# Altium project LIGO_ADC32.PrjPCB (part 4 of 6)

## Sheet AD32_PHASE.SchDoc: VCO & Phase Detector
size B; DocumentNumber: 1; Revision: C; SheetNumber: 2; SheetTotal: 17; SPICEModelCacheGRPSJKPR: <root> / <DocumentId>GRPSJKPR</DocumentId> / <CacheFrame Number="0"> / <Model Name="op284f" Kind="CKT"> / <Text>* OP284F SPICE Macro-model              11/95 / Rev. B / *                                       ARG / ADSC / * / * Revision History: / * / *     Rev. B / * Changed the short-circuit output current limit from +/- 7.5mA / * to +/- 6.5mA to reflect final data sheet limits. / * / * Changed Vos spec to conform to final data sheet value of / * 125uV, up from 50uV. / * / * / * This version of the OP284 model simulates the worst-case / * parameters of the 'F' grade.  The worst-case parameters / * used correspond to those in the data sheet. / * / * Copyright 1993 by Analog Devices / * / * Refer to "README.DOC" file for License Statement. Use of this model / * indicates your acceptance of the terms and provisions in the License / * Statement. / * / * Node assignments / *                non-inverting input / *                ¦   inverting input / *                ¦   ¦   positive supply / *                ¦   ¦   ¦   negative supply / *                ¦   ¦   ¦   ¦   output / *                ¦   ¦   ¦   ¦   ¦ / .SUBCKT OP284F   1   2   99  50  45 / * / * INPUT STAGE / * / Q1   5    2    3    QIN 1 / Q2   6    11   3    QIN 1 / Q3   7    2    4    QIP 1 / Q4   8    11   4    QIP 1 / DC1  2    11   DC / DC2  11   2    DC / Q5   4    9    99   QIP 1 / Q6   9    9    99   QIP 1 / Q7   3    10   50   QIN 1 / Q8   10   10   50   QIN 1 / R1   99   5    4E3 / R2   99   6    4E3 / R3   7    50   4E3 / R4   8    50   4E3 / IREF 9    10   50.5E-6 / EOS  1    11   POLY(2) (22,98) (14,98) -125E-6 501.2E-3 1 / IOS  2    1    25E-9 / CIN  1    2    2E-12 / GN1  98   1    17 98 1E-3 / GN2  98   2    23 98 1E-3 / * / * VOLTAGE NOISE SOURCE WITH FLICKER NOISE / * / VN1  13   98   DC 2 / VN2  98   15   DC 2 / DN1  13   14   DEN / DN2  14   15   DEN / * / * CURRENT NOISE SOURCE WITH FLICKER NOISE / * / VN3  16   98   DC 2 / VN4  98   18   DC 2 / DN3  16   17   DIN / DN4  17   18   DIN / * / * 2ND CURRENT NOISE SOURCE WITH FLICKER NOISE / * / VN5  19   98   DC 2 / VN6  98   24   DC 2 / DN5  19   23   DIN / DN6  23   24   DIN / * / * GAIN STAGE / * / EREF 98   0    POLY(2) (99,0) (50,0) 0 0.5 0.5 / G1   98   20   POLY(2) (6,5) (8,7) 0 0.5E-3 0.5E-3 / R9   20   98   1E3 / * / * COMMON MODE STAGE WITH ZERO AT 5KHZ / * / ECM  98   21   POLY(2) (1,98) (2,98) 0 0.5 0.5 / R10  21   22   1 / R11  22   98   100E-6 / C4   21   22   31.756E-6 / * / * NEGATIVE ZERO AT 20MHZ / * / E1   27   98   20 98 1 / R17  27   28   1 / R18  28   98   1E-6 / C8   25   26   7.958E-9 / ENZ  25   98   27 28 1 / VNZ  26   98   DC 0 / FNZ  27   28   VNZ -1 / * / * POLE AT 40MHZ / * / G4   98   29   28 98 1E6 / R19  29   98   1 / C9   29   98   3.979E-9 / * / * POLE AT 40MHZ / * / G5   98   30   29 98 1 / R20  30   98   1 / C10  30   98   3.979E-9 / * / * OUTUT STAGE / * / ISY  99   50   0.526E-3 / GIN  50   31   POLY(1) (30,98) 0.862574E-6 511.855E-6 / RIN  31   50   2.75E6 / VB   99   32   0.7 / Q11  32   31   33   QON 1 / R21  33   34   4.5E3 / I1   34   50   50E-6 / R22  99   35   6E3 / Q12  36   36   35   QOP 1 / I2   36   50   50E-6 / R23  99   37   2.6E3 / R24  34   38   5E3 / Q13  39   36   37   QOP 1 / Q14  39   38   40   QON 1.5 / R25  40   50   40 / Q15  39   39   41   QON 1 / R26  41   42   1E3 / R27  99   43   220 / Q16  44   44   43   QOP 1.5 / Q17  44   39   42   QON 1 / R28  42   50   2E3 / VSCP 99   97   DC 0 / FSCP 46   99   VSCP 1 / RSCP 46   99   125 / Q20  44   46   99   QOP 1 / Q18  45   44   97   QOP 4.5 / Q19  45   34   51   QON 4.5 / VSCN 51   50   DC 0 / FSCN 50   47   VSCN 1 / RSCN 47   50   122 / Q21  34   47   50   QON 1 / CC2  31   45   20E-12 / CF1  31   34   15E-12 / CF2  31   42   15E-12 / CO1  34   45   15E-12 / CO2  42   45   5E-12 / D3   45   99   DX / D4   50   45   DX / .MODEL DC D(IS=130E-21) / .MODEL DX D() / .MODEL DEN D(RS=100 KF=12E-15 AF=1) / .MODEL DIN D(RS=5.358 KF=56E-15 AF=1) / .MODEL QIN NPN(BF=250 VA=200 IS=0.5E-16) / .MODEL QIP PNP(BF=60 VA=100 IS=0.5E-16) / .MODEL QON NPN(BF=200 VA=200 IS=0.5E-16 RC=140) / .MODEL QOP PNP(BF=200 VA=200 IS=0.5E-16 RC=210) / .ENDS</Text> / </Model> / </CacheFrame> / </root>
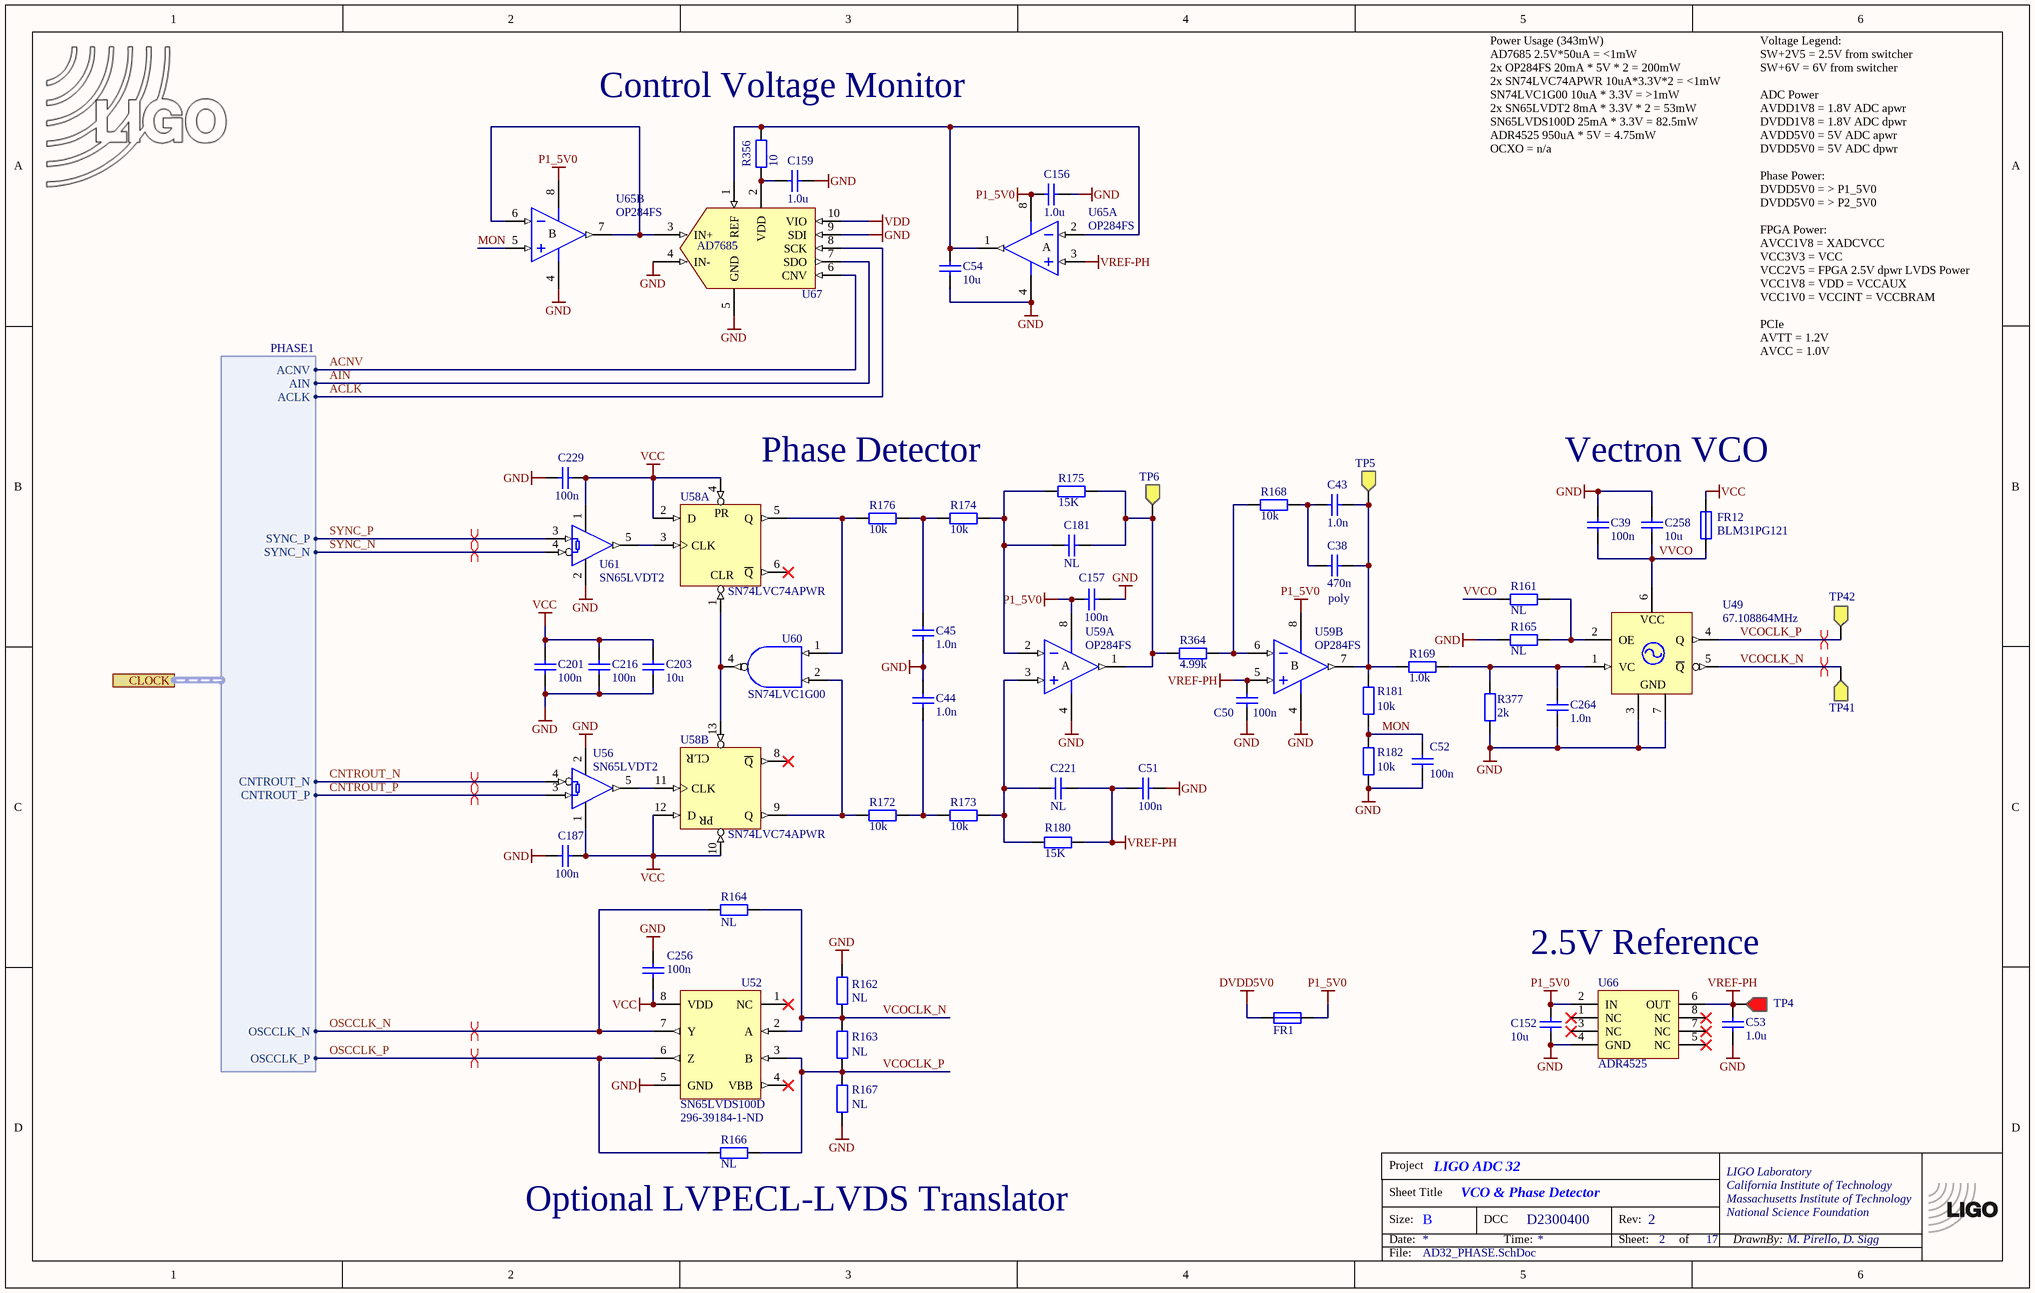
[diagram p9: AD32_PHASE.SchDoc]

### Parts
(Parts that share a designator on the sheet are numbered #1, #2 ... from top to bottom, then left to right.)
*?#6  TitleBlock  (value not drawn)  (graphical)
C38  470n  [ECQPZ120060-5.0]
C39  100n  [CC1005-0402]
C43  1.0n  [CC1005-0402]
C44  1.0n  [CC1005-0402]
C45  1.0n  [CC1005-0402]
C50  100n  [CC1005-0402]
C51  100n  [CC1005-0402]
C52  100n  [CC1005-0402]
C53  1.0u  [CC1608-0603]
C54  10u  [CC2013-0805]
C152  10u  [CC2013-0805]
C156  1.0u  [CC1608-0603]
C157  100n  [CC1005-0402]
C159  1.0u  [CC1608-0603]
C181  NL  [CC2013-0805]
C187  100n  [CC1005-0402]
C201  100n  [CC1005-0402]
C203  10u  [CC2013-0805]
C216  100n  [CC1005-0402]
C221  NL  [CC2013-0805]
C229  100n  [CC1005-0402]
C256  100n  [CC1005-0402]
C258  10u  [CC2013-0805]
C264  1.0n  [CC1005-0402]
FR1  BLM31PG121  [CC3216-1206]  (value not drawn)
FR12  BLM31PG121  [CC3216-1206]
LOGO2#1  LIGO logo  [LIGO_LOGO]  (value not drawn)  (graphical)
R161  NL  [CR1005-0402]
R162  NL  [CR1005-0402]
R163  NL  [CR1005-0402]
R164  NL  [CR1005-0402]
R165  NL  [CR1005-0402]
R166  NL  [CR1005-0402]
R167  NL  [CR1005-0402]
R168  10k  [CR1005-0402]
R169  1.0k  [CR1005-0402]
R172  10k  [CR1005-0402]
R173  10k  [CR1005-0402]
R174  10k  [CR1005-0402]
R175  15K  [CR1005-0402]
R176  10k  [CR1005-0402]
R180  15K  [CR1005-0402]
R181  10k  [CR1005-0402]
R182  10k  [CR1005-0402]
R356  10  [CR1005-0402]
R364  4.99k  [CR1005-0402]
R377  2k  [CR1005-0402]
TP4  Testpoint  [TP1-RED]  (value not drawn)
TP5  Testpoint  [TP1-YLW]  (value not drawn)
TP6  Testpoint  [TP1-YLW]  (value not drawn)
TP41  Testpoint  [TP2]  (value not drawn)
TP42  Testpoint  [TP2]  (value not drawn)
U49  67.108864MHz  [BomarSiTime]
U52  SN65LVDS100D  Supplier Part Number 1: 296-39184-1-ND  [MSOP8]
U56  SN65LVDT2  [SO-G5/E2.4]
U58  SN74LVC74APWR  [TSSOP14]  (parts A,B of 2)
U59  OP284FS  [SO-8_N]  (parts A,B of 2)
U60  SN74LVC1G00  [SO-G5/E2.4]
U61  SN65LVDT2  [SO-G5/E2.4]
U65  OP284FS  [SO-8_N]  (parts A,B of 2)
U66  ADR4525  [SO-G8]
U67  AD7685  [TSSO3x5-G10]

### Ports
CLOCK (harness PHASE1)

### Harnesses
PHASE1: OSCCLK_N, OSCCLK_P, CNTROUT_N, CNTROUT_P, SYNC_N, SYNC_P, ACLK, ACNV, AIN

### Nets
DVDD5V0: FR1.2
GND: C39.1 C44.1 C45.2 C50.1 C51.1 C52.1 C53.1 C54.2 C152.2 C156.1 C157.1 C159.1 C187.1 C201.1 C203.2 C216.1 C229.1 C256.1 C258.1 C264.2 R162.1 R165.1 R167.2 R182.2 R377.2 U49.3(GND1) U49.7(EP) U52.5(GND) U56.2(GND) U58.7(GND) U59.4(V-) U60.3(GND) U61.2(GND) U65.4(V-) U66.4(GND) U67.4(IN-) U67.5(GND) U67.9(SDI)
P1_5V0: C152.1 C156.2 C157.2 FR1.1 U59.8(V+) U65.8(V+) U66.2(IN)
VCC: C187.2 C201.2 C203.1 C216.2 C229.2 C256.2 FR12.2 U52.8(VDD) U56.1(VCC) U58.2(D) U58.4(PR) U58.10(PR) U58.12(D) U58.14(VCC) U60.5(VCC) U61.1(VCC)
VDD: U67.10(VIO)  [project net VCC1V8]
VREF-PH: C50.2 C51.2 C53.2 C221.1 R180.2 TP4.1 U59.5(IN+) U65.3(IN+) U66.6(OUT)
ACLK: U67.8(SCK) ; port CLOCK.ACLK  [project net CLOCK.ACLK]
ACNV: U67.6(CNV) ; port CLOCK.ACNV  [project net CLOCK.ACNV]
AIN: U67.7(SDO) ; port CLOCK.AIN  [project net CLOCK.AIN]
CNTROUT_N: U56.4(B) ; port CLOCK.CNTROUT_N  [project net CLOCK.CNTROUT_N]
CNTROUT_P: U56.3(A) ; port CLOCK.CNTROUT_P  [project net CLOCK.CNTROUT_P]
MON: C52.2 R181.2 R182.1 U65.5(IN+)
OSCCLK_N: R164.1 U52.7(Y) ; port CLOCK.OSCCLK_N  [project net CLOCK.OSCCLK_N]
OSCCLK_P: R166.2 U52.6(Z) ; port CLOCK.OSCCLK_P  [project net CLOCK.OSCCLK_P]
SYNC_N: U61.4(B) ; port CLOCK.SYNC_N  [project net CLOCK.SYNC_N]
SYNC_P: U61.3(A) ; port CLOCK.SYNC_P  [project net CLOCK.SYNC_P]
VCOCLK_N: R162.2 R163.1 R164.2 TP41.1 U49.5(~{Q}) U52.2(A)
VCOCLK_P: R163.2 R166.1 R167.1 TP42.1 U49.4(Q) U52.3(B)
VVCO: C39.2 C258.2 FR12.1 R161.1 U49.6(VDD)
NetC38_1: C38.1 C43.2 R168.2
NetC38_2: C38.2 C43.1 R169.2 R181.1 TP5.1 U59.7(OUT)
NetC44_2: C44.2 R172.2 R173.1
NetC45_1: C45.1 R174.1 R176.2
NetC54_1: C54.1 R356.2 U65.1(OUT) U65.2(IN-) U67.1(REF)
NetC159_2: C159.2 R356.1 U67.2(VDD)
NetC181_1: C181.1 R175.2 R364.1 TP6.1 U59.1(OUT)
NetC181_2: C181.2 R174.2 R175.1 U59.2(IN-)
NetC221_2: C221.2 R173.2 R180.1 U59.3(IN+)
NetC264_1: C264.1 R169.1 R377.1 U49.1(VC)
NetR161_2: R161.2 R165.2 U49.2(OE)
NetR168_1: R168.1 R364.2 U59.6(IN-)
NetR172_1: R172.1 U58.9(Q) U60.2
NetR176_1: R176.1 U58.5(Q) U60.1
NetU56_5: U56.5(R) U58.11(CLK)
NetU58_1: U58.1(CLR) U58.13(CLR) U60.4
NetU58_3: U58.3(CLK) U61.5(R)
NetU65_6: U65.6(IN-) U65.7(OUT) U67.3(IN+)

Not connected (* = marked no-connect by the designer): U52 1(NC)* 4(VBB)*; U58 6(~{Q})* 8(~{Q})*; U66 1(NC)* 3(NC)* 5(NC)* 7(NC)* 8(NC)*

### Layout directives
differential pair: CLOCK.CNTROUT_N, CLOCK.CNTROUT_P, CLOCK.OSCCLK_N, CLOCK.OSCCLK_P, CLOCK.SYNC_N, CLOCK.SYNC_P, VCOCLK_N, VCOCLK_P

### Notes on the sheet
- (near R356) Control Voltage Monitor
- Power Usage (343mW)
  AD7685 2.5V*50uA = <1mW
  2x OP284FS 20mA * 5V * 2 = 200mW
  2x SN74LVC74APWR 10uA*3.3V*2 = <1mW
  SN74LVC1G00 10uA * 3.3V = >1mW
  2x SN65LVDT2 8mA * 3.3V * 2 = 53mW
  SN65LVDS100D 25mA * 3.3V = 82.5mW
  ADR4525 950uA * 5V = 4.75mW
  OCXO = n/a
- Voltage Legend:
  SW+2V5 = 2.5V from switcher
  SW+6V = 6V from switcher
  ADC Power
  AVDD1V8 = 1.8V ADC apwr
  DVDD1V8 = 1.8V ADC dpwr
  AVDD5V0 = 5V ADC apwr
  DVDD5V0 = 5V ADC dpwr
  Phase Power:
  DVDD5V0 = > P1_5V0
  DVDD5V0 = > P2_5V0
  FPGA Power:
  AVCC1V8 = XADCVCC
  VCC3V3 = VCC
  VCC2V5 = FPGA 2.5V dpwr LVDS Power
  VCC1V8 = VDD = VCCAUX
  VCC1V0 = VCCINT = VCCBRAM
  PCIe
  AVTT = 1.2V
  AVCC = 1.0V
- Phase Detector
- Vectron VCO
- poly
- 2.5V Reference
- (near R166) Optional LVPECL-LVDS Translator

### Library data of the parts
C38 = CapPolypropylene ECQPZ: Polypropylene Film Capacitor, radial lead; Part Number: 399-13063-ND
C39 C50-C52 C157 C187 C201 C216 C229 C256 = ChipCap: C0402 100n; Part Number: CL05B104KA5NNNC
C43-C45 C264 = ChipCap: C0402 1.0n; Part Number: 0402N102J250CT
C53 C156 C159 = ChipCap: C0603 1.0u; Part Number: CL10B105KA8NNNC
C54 C152 C203 C258 = ChipCap: C0805 10u; Part Number: CL21A106KAYNNNG
C181 C221 = ChipCap: C0805 NL
FR1 FR12 = BLM31PG121SN1: ferrite bead, 120Ohm at 100MHz, 1206; Part Number: BLM31PG121SN1L
LOGO2#1 = LIGO_logo
R161 R165 = ChipRes1: R0603 NL
R162-R164 R166 R167 = ChipRes1: R0402 NL
R168 R172-R174 R176 R181 R182 = ChipRes1: R0402 10k; Part Number: ERA-2AEB103X
R169 = ChipRes1: R0402 1.0k; Part Number: RT0402BRD071KL
R175 R180 = ChipRes1: R0402 15k; Part Number: ERA-2AEB153X
R356 = ChipRes1: R0402 10; Part Number: RP73PF1E10RBTD
R364 = ChipRes1: R0402 4.99k; Part Number: RR0510P-4991-D
R377 = ChipRes1: R0402 2k; Part Number: ERA-2AEB202X
TP4 = TP_POSITIVE: Testpoint, red; Part Number: Keystone / 5000
TP5 TP6 = TP_SIGNAL: Testpoint, yellow; Part Number: Keystone / 5004
TP41 TP42 = TP_SIGNAL: Part Number: Keystone / 5017
U49 = VCXO_BomarSiTime: Voltage controlled crystal oscillator, differential output, Bomar 14.3 x 8.7mm, or SiTime 7.0 x 5.0mm; Part Number: B1815-BA0S36LK-67.108864; Alternate Part 1: SiT3372AI-1E2-xxxx000.fp0000f; Alternate Part 2: SiT3372AI-2E2-33NC47.934903; Alternate Part 3: C5310-D105-SV033-RFL-B1-67.108864MHz
U52 = SN65LVDS100: DIFF TRANSLATOR
U56 U61 = SN65LVDT2DBV: Single LVDS Receiver with 100 Ohm termination; Part Number: 296-6896-1-ND
U58 = 74F74PC: Dual D-Type Positive Edge-Triggered Flip-Flop
U59 U65 = OP284FS: Precision Rail-to-Rail Input and Output Operational Amplifier; Part Number: OP284FSZ-REEL7
U60 = SN74LVC1G00: Part Number: 74LVC1G00W5-7
U66 = ADR292ER: Low-Noise Micropower Precision Voltage Reference; Part Number: ADR425ARZ-ND
U67 = AD7685: 16 bit ADC, 250kSPS, pseudo differential, serial; Part Number: AD7685BRMZRL7

## Sheet AD32_PCIE_HL.SchDoc: PCIe Interface
size B; Engineer: Daniel Sigg; DocumentNumber: 1; Revision: C; SheetNumber: 16; SheetTotal: 17; PageSetup: Record=PageOptions¦CenterHorizontal=True¦CenterVertical=True¦PrintScale=0.72¦XCorrection=1.00¦YCorrection=1.00¦PrintKind=0¦BorderSize=5000000¦LeftOffset=0¦BottomOffset=0¦Orientation=2¦PaperLength=1000¦PaperWidth=1000¦Scale=100¦PaperSource=7¦PrintQuality=-4¦MediaType=1¦DitherType=10¦PaperKind=Tabloid¦PrintScaleMode=1
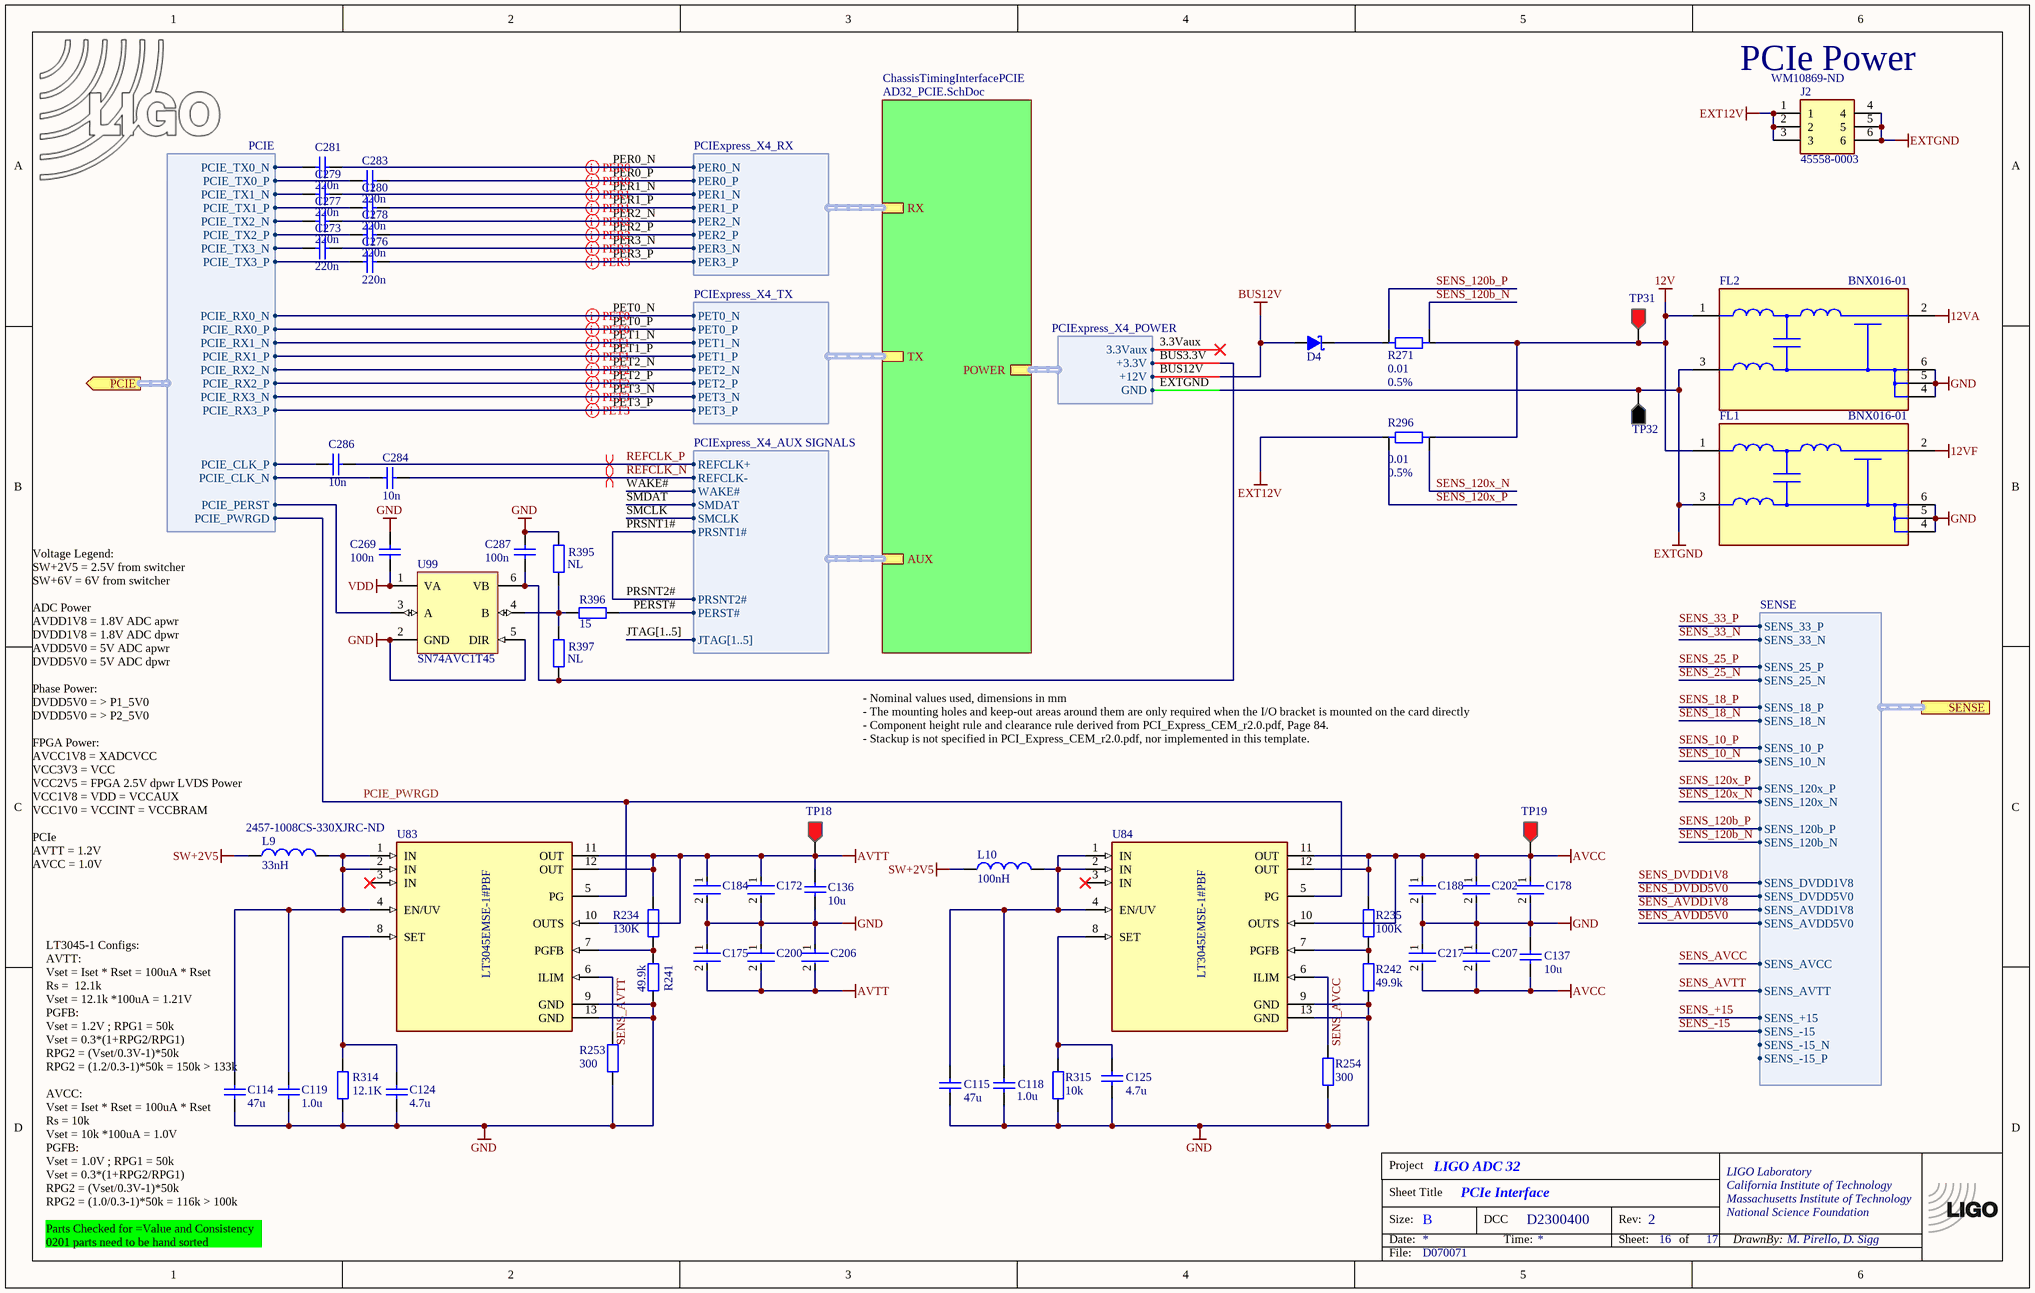
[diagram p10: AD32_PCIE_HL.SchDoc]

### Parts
(Parts that share a designator on the sheet are numbered #1, #2 ... from top to bottom, then left to right.)
*?#7  TitleBlock  (value not drawn)  (graphical)
C114  47u  [CC3216-1206]
C115  47u  [CC3216-1206]
C118  1.0u  [CC1608-0603]
C119  1.0u  [CC1608-0603]
C124  4.7u  [CC1608-0603]
C125  4.7u  [CC1608-0603]
C136  10u  [CC2013-0805]
C137  10u  [CC2013-0805]
C172  470n  [FP-CL03-IPC_B]  (value not drawn)
C175  470n  [FP-CL03-IPC_B]  (value not drawn)
C178  470n  [FP-CL03-IPC_B]  (value not drawn)
C184  470n  [FP-CL03-IPC_B]  (value not drawn)
C188  470n  [FP-CL03-IPC_B]  (value not drawn)
C200  470n  [FP-CL03-IPC_B]  (value not drawn)
C202  470n  [FP-CL03-IPC_B]  (value not drawn)
C206  470n  [FP-CL03-IPC_B]  (value not drawn)
C207  470n  [FP-CL03-IPC_B]  (value not drawn)
C217  470n  [FP-CL03-IPC_B]  (value not drawn)
C269  100n  [CC1005-0402]
C273  220n  [CC1005-0402]
C276  220n  [CC1005-0402]
C277  220n  [CC1005-0402]
C278  220n  [CC1005-0402]
C279  220n  [CC1005-0402]
C280  220n  [CC1005-0402]
C281  220n  [CC1005-0402]
C283  220n  [CC1005-0402]
C284  10n  [CC1005-0402]
C286  10n  [CC1005-0402]
C287  100n  [CC1005-0402]
D4  Schottky SMB  [DO-SMB]  (value not drawn)
FL1  BNX016-01  [FP-BNX_L12MM2_W11MM2_T8MM-MFG]
FL2  BNX016-01  [FP-BNX_L12MM2_W11MM2_T8MM-MFG]
J2  45558-0003  Supplier Part Number 1: WM10869-ND  [455580003]
L9  Supplier Part Number 1: 2457-1008CS-330XJRC-ND  [CL2520-1008]  (hidden comment: 33nH)
L10  100nH  [CL2520-1008]
LOGO?#2  LIGO logo  [LIGO_LOGO]  (value not drawn)  (graphical)
R234  130K  [CR1005-0402]
R235  100K  [CR1005-0402]
R241  49.9k  [CR1005-0402]
R242  49.9k  [CR1005-0402]
R253  300  [CR1005-0402]
R254  300  [CR1005-0402]
R271  Tolerance: 0.5%  [CR0816-0306-4P]  (hidden comment: 0.01)
R296  Tolerance: 0.5%  [CR0816-0306-4P]  (hidden comment: 0.01)
R314  12.1K  [CR1005-0402]
R315  10k  [CR1005-0402]
R395  NL  [CR1005-0402]
R396  15  [CR1005-0402]
R397  NL  [CR1005-0402]
TP18  Testpoint  [TP1-RED]  (value not drawn)
TP19  Testpoint  [TP1-RED]  (value not drawn)
TP31  Testpoint  [TP1-RED]  (value not drawn)
TP32  Testpoint  [TP1-BLK]  (value not drawn)
U83  LT3045EMSE-1#PBF  [FP-MSE-12-05-08-1666-IPC_B]
U84  LT3045EMSE-1#PBF  [FP-MSE-12-05-08-1666-IPC_B]
U99  SN74AVC1T45  [SO-G6/E2.4]

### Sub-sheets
ChassisTimingInterfacePCIE = AD32_PCIE.SchDoc: RX (harness PCIExpress_X4_RX), TX (harness PCIExpress_X4_TX), AUX (harness PCIExpress_X4_AUX SIGNALS), POWER (harness PCIExpress_X4_POWER)

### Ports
PCIE (out, harness PCIE), SENSE (harness SENSE)

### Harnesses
PCIE: PCIE_CLK_N, PCIE_CLK_P, PCIE_RX0_N, PCIE_RX0_P, PCIE_TX0_N, PCIE_TX0_P, PCIE_PERST, PCIE_PWRGD, PCIE_TX1_N, PCIE_TX1_P, PCIE_TX2_P, PCIE_TX2_N, PCIE_TX3_P, PCIE_TX3_N, PCIE_RX1_N, PCIE_RX1_P, PCIE_RX2_N, PCIE_RX2_P, PCIE_RX3_N, PCIE_RX3_P
PCIExpress_X4_POWER: +3.3V, +12V, GND, 3.3Vaux
PCIExpress_X4_AUX SIGNALS: JTAG[1..5], PERST#, PRSNT1#, PRSNT2#, REFCLK+, REFCLK-, SMCLK, SMDAT, WAKE#
PCIExpress_X4_RX: PER0_N, PER0_P, PER1_N, PER1_P, PER2_N, PER2_P, PER3_N, PER3_P
PCIExpress_X4_TX: PET0_N, PET0_P, PET1_N, PET1_P, PET2_N, PET2_P, PET3_N, PET3_P
SENSE: SENS_33_P, SENS_33_N, SENS_25_P, SENS_25_N, SENS_18_P, SENS_18_N, SENS_10_P, SENS_10_N, SENS_120x_P, SENS_120x_N, SENS_120b_P, SENS_120b_N, SENS_DVDD1V8, SENS_DVDD5V0, SENS_AVDD1V8, SENS_+15, SENS_-15, SENS_AVTT, SENS_AVCC, SENS_-15_N, SENS_-15_P, SENS_AVDD5V0

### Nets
12V: FL1.1(B) FL2.1(B) R271.1 R296.4 TP31.1
12VA: FL2.2(CB)
12VF: FL1.2(CB)
AVCC: C137.1 C178.1 C188.1 C202.1 C207.2 C217.2 R235.2 TP19.1 U84.10(OUTS) U84.11(OUT) U84.12(OUT)
AVTT: C136.2 C172.1 C175.2 C184.1 C200.2 C206.2 R234.2 TP18.1 U83.10(OUTS) U83.11(OUT) U83.12(OUT)
BUS3.3V: C287.1 R397.2 U99.6(VB) ; sheet ChassisTimingInterfacePCIE/POWER.+3.3V
BUS12V: D4.1(A) ; sheet ChassisTimingInterfacePCIE/POWER.+12V
EXT12V: J2.1 J2.2 J2.3 R296.1
EXTGND: FL1.3(PSG) FL2.3(PSG) J2.4 J2.5 J2.6 TP32.1 ; sheet ChassisTimingInterfacePCIE/POWER.GND
GND: C114.1 C115.1 C118.1 C119.1 C124.1 C125.1 C136.1 C137.2 C172.2 C175.1 C178.2 C184.2 C188.2 C200.1 C202.2 C206.1 C207.1 C217.1 C269.2 C287.2 FL1.4(CG) FL1.5(CG) FL1.6(CG) FL2.4(CG) FL2.5(CG) FL2.6(CG) R241.1 R242.1 R253.1 R254.1 R314.1 R315.1 R395.1 U83.9(GND) U83.13(GND) U84.9(GND) U84.13(GND) U99.2(GND) U99.5(DIR)
SENS_18_N: C269.1 U99.1(VA) ; port SENSE.SENS_18_N  [also labelled VDD]  [project net VCC1V8]
SW+2V5: L9.1 L10.1
PCIE.PCIE_CLK_N: C284.2 ; port PCIE.PCIE_CLK_N
PCIE.PCIE_CLK_P: C286.2 ; port PCIE.PCIE_CLK_P
PCIE.PCIE_PERST: U99.3(A) ; port PCIE.PCIE_PERST
PCIE.PCIE_TX0_N: C281.2 ; port PCIE.PCIE_TX0_N
PCIE.PCIE_TX0_P: C283.2 ; port PCIE.PCIE_TX0_P
PCIE.PCIE_TX1_N: C279.2 ; port PCIE.PCIE_TX1_N
PCIE.PCIE_TX1_P: C280.2 ; port PCIE.PCIE_TX1_P
PCIE.PCIE_TX2_N: C277.2 ; port PCIE.PCIE_TX2_N
PCIE.PCIE_TX2_P: C278.2 ; port PCIE.PCIE_TX2_P
PCIE.PCIE_TX3_N: C273.2 ; port PCIE.PCIE_TX3_N
PCIE.PCIE_TX3_P: C276.2 ; port PCIE.PCIE_TX3_P
PCIE_PWRGD: U83.5(PG) U84.5(PG) ; port PCIE.PCIE_PWRGD  [project net PCIE.PCIE_PWRGD]
PER0_N: C281.1 ; sheet ChassisTimingInterfacePCIE/RX.PER0_N
PER0_P: C283.1 ; sheet ChassisTimingInterfacePCIE/RX.PER0_P
PER1_N: C279.1 ; sheet ChassisTimingInterfacePCIE/RX.PER1_N
PER1_P: C280.1 ; sheet ChassisTimingInterfacePCIE/RX.PER1_P
PER2_N: C277.1 ; sheet ChassisTimingInterfacePCIE/RX.PER2_N
PER2_P: C278.1 ; sheet ChassisTimingInterfacePCIE/RX.PER2_P
PER3_N: C273.1 ; sheet ChassisTimingInterfacePCIE/RX.PER3_N
PER3_P: C276.1 ; sheet ChassisTimingInterfacePCIE/RX.PER3_P
PERST#: R396.1 ; sheet ChassisTimingInterfacePCIE/AUX.PERST#
PET0_N: port PCIE.PCIE_RX0_N, sheet ChassisTimingInterfacePCIE/TX.PET0_N  [project net PCIE.PCIE_RX0_N]
PET0_P: port PCIE.PCIE_RX0_P, sheet ChassisTimingInterfacePCIE/TX.PET0_P  [project net PCIE.PCIE_RX0_P]
PET1_N: port PCIE.PCIE_RX1_N, sheet ChassisTimingInterfacePCIE/TX.PET1_N  [project net PCIE.PCIE_RX1_N]
PET1_P: port PCIE.PCIE_RX1_P, sheet ChassisTimingInterfacePCIE/TX.PET1_P  [project net PCIE.PCIE_RX1_P]
PET2_N: port PCIE.PCIE_RX2_N, sheet ChassisTimingInterfacePCIE/TX.PET2_N  [project net PCIE.PCIE_RX2_N]
PET2_P: port PCIE.PCIE_RX2_P, sheet ChassisTimingInterfacePCIE/TX.PET2_P  [project net PCIE.PCIE_RX2_P]
PET3_N: port PCIE.PCIE_RX3_N, sheet ChassisTimingInterfacePCIE/TX.PET3_N  [project net PCIE.PCIE_RX3_N]
PET3_P: port PCIE.PCIE_RX3_P, sheet ChassisTimingInterfacePCIE/TX.PET3_P  [project net PCIE.PCIE_RX3_P]
PRSNT1#: sheet ChassisTimingInterfacePCIE/AUX.PRSNT1#, sheet ChassisTimingInterfacePCIE/AUX.PRSNT2#  [also labelled PRSNT2#]
REFCLK_N: C284.1 ; sheet ChassisTimingInterfacePCIE/AUX.REFCLK-
REFCLK_P: C286.1 ; sheet ChassisTimingInterfacePCIE/AUX.REFCLK+
SENS_120b_N: R271.2 ; port SENSE.SENS_120b_N  [project net SENSE.SENS_120b_N]
SENS_120b_P: R271.3 ; port SENSE.SENS_120b_P  [project net SENSE.SENS_120b_P]
SENS_120x_N: R296.3 ; port SENSE.SENS_120x_N  [project net SENSE.SENS_120x_N]
SENS_120x_P: R296.2 ; port SENSE.SENS_120x_P  [project net SENSE.SENS_120x_P]
SENS_AVCC: R254.2 U84.6(ILIM) ; port SENSE.SENS_AVCC  [project net SENSE.SENS_AVCC]
SENS_AVTT: R253.2 U83.6(ILIM) ; port SENSE.SENS_AVTT  [project net SENSE.SENS_AVTT]
NetC114_2: C114.2 C119.2 L9.2 U83.1(IN) U83.2(IN) U83.4(EN/UV)
NetC115_2: C115.2 C118.2 L10.2 U84.1(IN) U84.2(IN) U84.4(EN/UV)
NetC124_2: C124.2 R314.2 U83.8(SET)
NetC125_2: C125.2 R315.2 U84.8(SET)
NetD4_2: D4.2(K) R271.4
NetR234_1: R234.1 R241.2 U83.7(PGFB)
NetR235_1: R235.1 R242.2 U84.7(PGFB)
NetR395_2: R395.2 R396.2 R397.1 U99.4(B)

Not connected (* = marked no-connect by the designer): U83 3(IN)*; U84 3(IN)*

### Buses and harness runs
bus JTAG[1..5]

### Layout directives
differential pair: PCIE.PCIE_RX0_N, PCIE.PCIE_RX0_P, PCIE.PCIE_RX1_N, PCIE.PCIE_RX1_P, PCIE.PCIE_RX2_N, PCIE.PCIE_RX2_P, PCIE.PCIE_RX3_N, PCIE.PCIE_RX3_P, PER0_N, PER0_P, PER1_N, PER1_P, PER2_N, PER2_P, PER3_N, PER3_P, REFCLK_N, REFCLK_P

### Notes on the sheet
- (near J2) PCIe Power
- - Nominal values used, dimensions in mm
  - The mounting holes and keep-out areas around them are only required when the I/O bracket is mounted on the card directly
  - Component height rule and clearance rule derived from PCI_Express_CEM_r2.0.pdf, Page 84.
  - Stackup is not specified in PCI_Express_CEM_r2.0.pdf, nor implemented in this template.
- (near L9) Voltage Legend:
  SW+2V5 = 2.5V from switcher
  SW+6V = 6V from switcher
  ADC Power
  AVDD1V8 = 1.8V ADC apwr
  DVDD1V8 = 1.8V ADC dpwr
  AVDD5V0 = 5V ADC apwr
  DVDD5V0 = 5V ADC dpwr
  Phase Power:
  DVDD5V0 = > P1_5V0
  DVDD5V0 = > P2_5V0
  FPGA Power:
  AVCC1V8 = XADCVCC
  VCC3V3 = VCC
  VCC2V5 = FPGA 2.5V dpwr LVDS Power
  VCC1V8 = VDD = VCCAUX
  VCC1V0 = VCCINT = VCCBRAM
  PCIe
  AVTT = 1.2V
  AVCC = 1.0V
- Parts Checked for =Value and Consistency
  0201 parts need to be hand sorted
- (near C114) LT3045-1 Configs:
  AVTT:
  Vset = Iset * Rset = 100uA * Rset
  Rs =  12.1k
  Vset = 12.1k *100uA = 1.21V
  PGFB:
  Vset = 1.2V ; RPG1 = 50k
  Vset = 0.3*(1+RPG2/RPG1)
  RPG2 = (Vset/0.3V-1)*50k
  RPG2 = (1.2/0.3-1)*50k = 150k > 133k
  AVCC:
  Vset = Iset * Rset = 100uA * Rset
  Rs = 10k
  Vset = 10k *100uA = 1.0V
  PGFB:
  Vset = 1.0V ; RPG1 = 50k
  Vset = 0.3*(1+RPG2/RPG1)
  RPG2 = (Vset/0.3V-1)*50k
  RPG2 = (1.0/0.3-1)*50k = 116k > 100k

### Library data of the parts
C114 C115 = ChipCap: C1206 47u; Part Number: C3216X5R1E476M160AC
C118 C119 = ChipCap: C0603 1.0u; Part Number: CL10B105KA8NNNC
C124 C125 = ChipCap: C0603 4.7u; Part Number: CL10B475KQ8NQNC
C136 C137 = ChipCap: C0805 10u; Part Number: CL21A106KAYNNNG
C172 C175 C178 C184 C188 C200 C202 C206 C207 C217 = CMP-2010-00306-2: C0201 470n; Part Number: CL03A474KQ3NNNC
C269 C287 = ChipCap: C0402 100n; Part Number: CL05B104KA5NNNC
C273 C276-C281 C283 = ChipCap: C0402 220n; Part Number: TMK105B7224KV-FR
C284 C286 = ChipCap: C0402 10n; Part Number: CC0402KRX7R9BB103
D4 = DIODE_SHOTTKY: Part Number: LSM115JE3/TR13
FL1 FL2 = CMP-2000-05960-2: FILTER LC TH
J2 = 45558-0003: Connector
L9 = ChipInductor: Inductor; Part Number: 1008CS-330XJRC
L10 = ChipInductor: Inductor; Part Number: 1008CS-101XJRC
LOGO?#2 = LIGO_logo
R234 = ChipRes1: R0402 130k; Part Number: RP73PF1E130KBTD
R235 = ChipRes1: R0402 100k; Part Number: ERA-2AEB104X
R241 R242 = ChipRes1: R0402 49.9k; Part Number: RR0510P-4992-D
R253 R254 = ChipRes1: R0402 300; Part Number: RR05P300DCT-ND
R271 R296 = RW1S0CK: Four-Terminal Current Sense Resistor
R314 = ChipRes1: R0402 12.1k; Part Number: ERA-2AEB1212X
R315 = ChipRes1: R0402 10k; Part Number: ERA-2AEB103X
R395 R397 = ChipRes1: R0402 NL
R396 = ChipRes1: R0402 15; Part Number: ERA-2AKD150X
TP18 TP19 TP31 = TP_POSITIVE: as TP4 on sheet AD32_PHASE
TP32 = TP_GND: Testpoint, black; Part Number: Keystone / 5001
U83 U84 = CMP-09138-000053-1: IC REG LINEAR 0V 500MA 12MSOP
U99 = SN74LVC1T45: Single-Bit Dual Supply Transceiver; Part Number: SN74AVC1T45DBVT

## Sheet AD32_PCIE.SchDoc: PCIe
size B; Engineer: Daniel Sigg; DocumentNumber: 1; Revision: C; SheetNumber: 17; SheetTotal: 17; PageSetup: Record=PageOptions¦CenterHorizontal=True¦CenterVertical=True¦PrintScale=0.72¦XCorrection=1.00¦YCorrection=1.00¦PrintKind=0¦BorderSize=5000000¦LeftOffset=0¦BottomOffset=0¦Orientation=2¦PaperLength=1000¦PaperWidth=1000¦Scale=100¦PaperSource=7¦PrintQuality=-4¦MediaType=1¦DitherType=10¦PaperKind=Tabloid¦PrintScaleMode=1
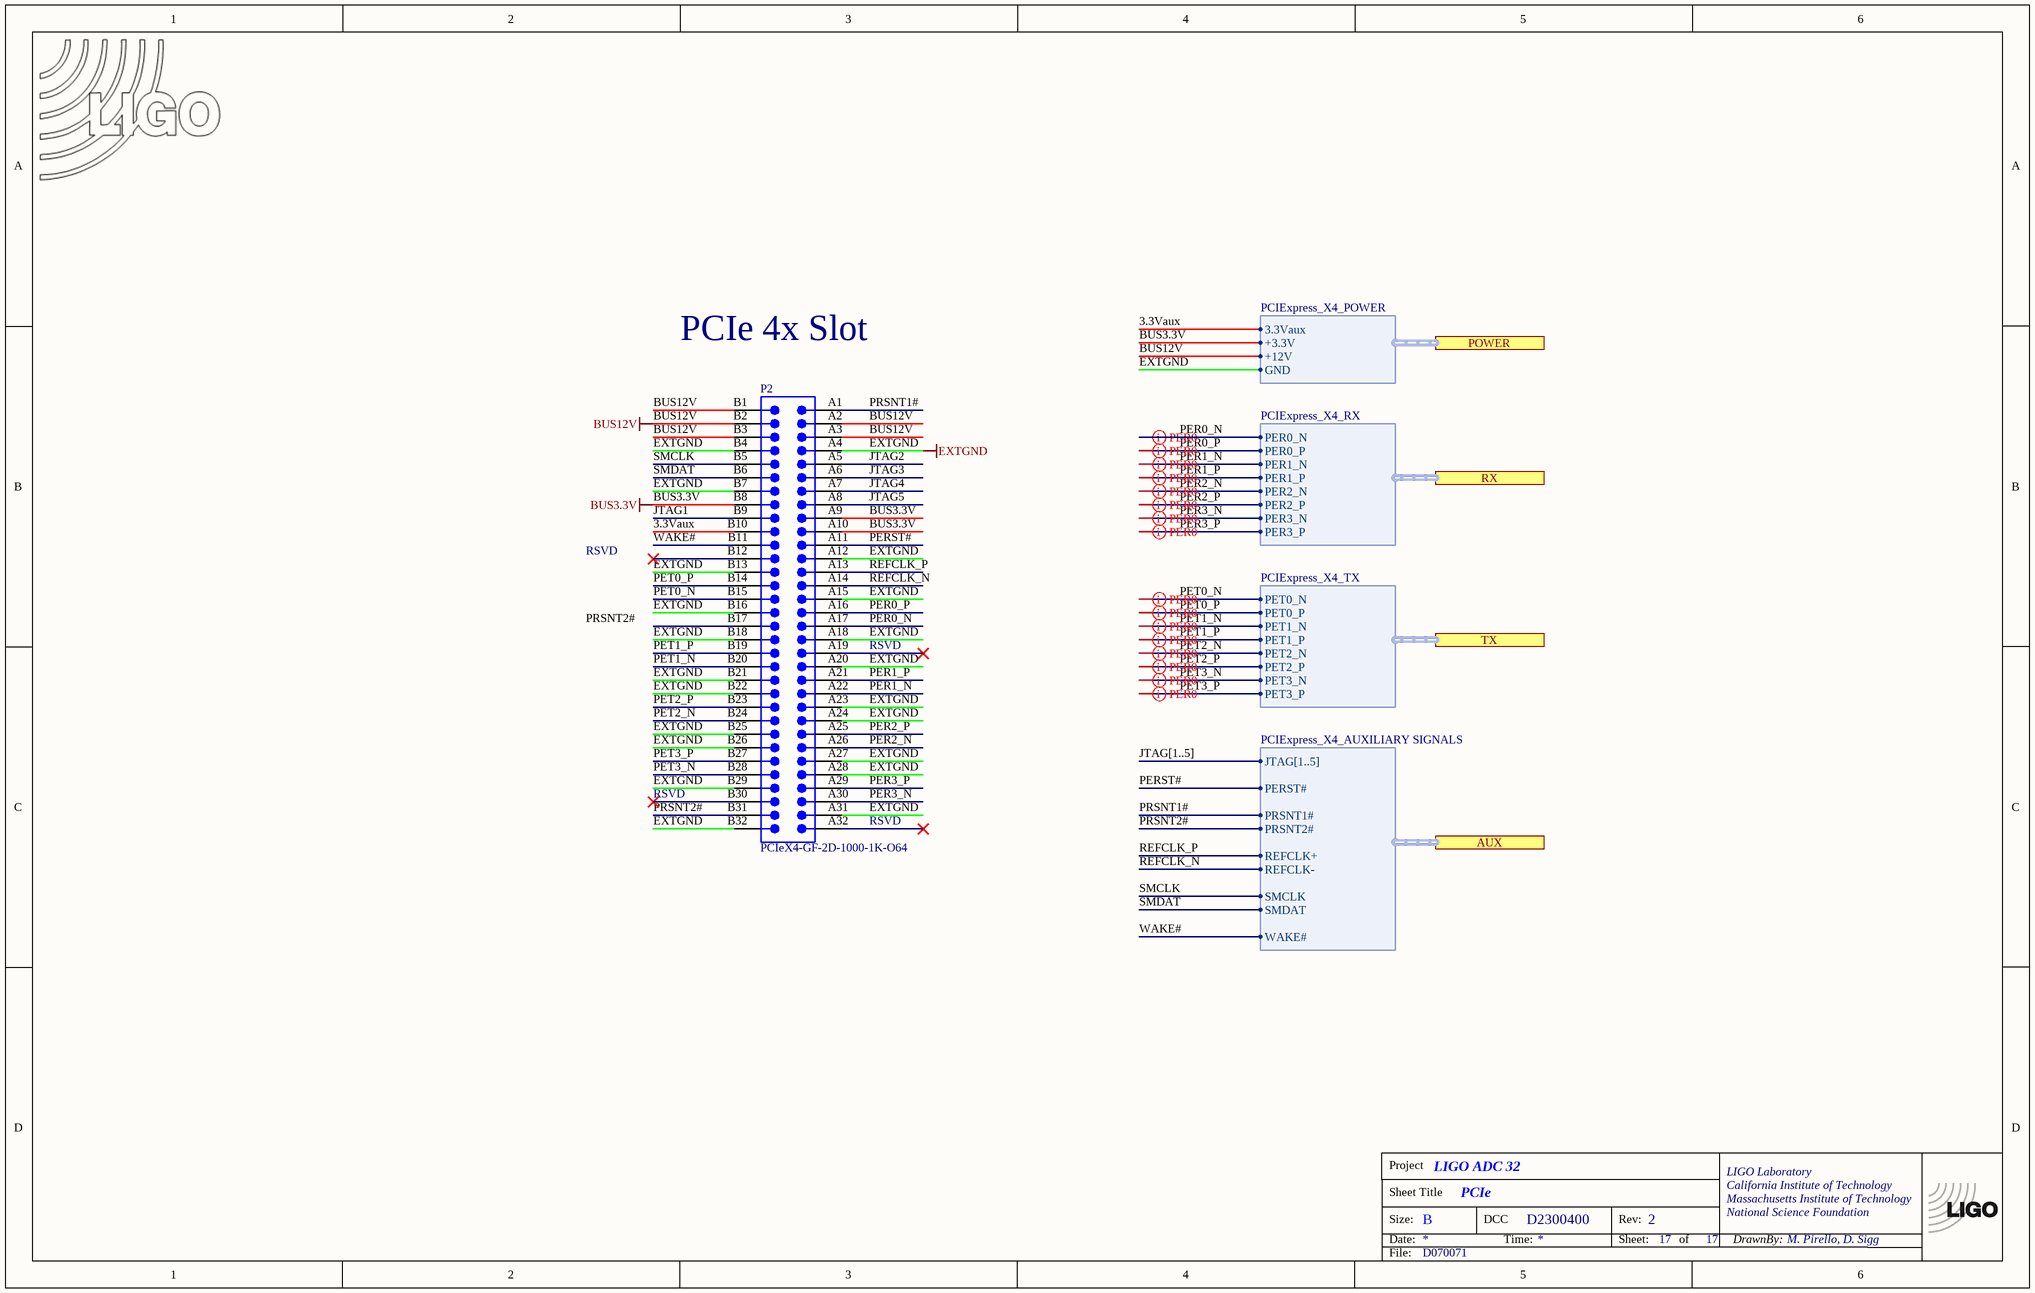
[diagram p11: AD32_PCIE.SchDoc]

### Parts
(Parts that share a designator on the sheet are numbered #1, #2 ... from top to bottom, then left to right.)
*?#8  TitleBlock  (value not drawn)  (graphical)
LOGO?#3  LIGO logo  [LIGO_LOGO]  (value not drawn)  (graphical)
P2  PCIeX4-GF-2D-1000-1K-O64  [PCIeX4-GF-2D-1000-1K-O64]  (no BOM)

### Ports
AUX (harness PCIExpress_X4_AUXILIARY SIGNALS), POWER (harness PCIExpress_X4_POWER), RX (harness PCIExpress_X4_RX), TX (harness PCIExpress_X4_TX)

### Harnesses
PCIExpress_X4_RX: PER0_N, PER0_P, PER1_N, PER1_P, PER2_N, PER2_P, PER3_N, PER3_P
PCIExpress_X4_TX: PET0_N, PET0_P, PET1_N, PET1_P, PET2_N, PET2_P, PET3_N, PET3_P
PCIExpress_X4_POWER: +3.3V, +12V, GND, 3.3Vaux
PCIExpress_X4_AUXILIARY SIGNALS: JTAG[1..5], PERST#, PRSNT1#, PRSNT2#, REFCLK+, REFCLK-, SMCLK, SMDAT, WAKE#

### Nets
BUS3.3V: P2.A9 P2.A10 P2.B8 ; port POWER.+3.3V
BUS12V: P2.A2 P2.A3 P2.B1 P2.B2 P2.B3 ; port POWER.+12V
EXTGND: P2.A4 P2.A12 P2.A15 P2.A18 P2.A20 P2.A23 P2.A24 P2.A27 P2.A28 P2.A31 P2.B4 P2.B7 P2.B13 P2.B16 P2.B18 P2.B21 P2.B22 P2.B25 P2.B26 P2.B29 P2.B32 ; port POWER.GND
3.3Vaux: P2.B10 ; port POWER.3.3Vaux
JTAG1: P2.B9
JTAG2: P2.A5
JTAG3: P2.A6
JTAG4: P2.A7
JTAG5: P2.A8
PER0_N: P2.A17 ; port RX.PER0_N
PER0_P: P2.A16 ; port RX.PER0_P
PER1_N: P2.A22 ; port RX.PER1_N
PER1_P: P2.A21 ; port RX.PER1_P
PER2_N: P2.A26 ; port RX.PER2_N
PER2_P: P2.A25 ; port RX.PER2_P
PER3_N: P2.A30 ; port RX.PER3_N
PER3_P: P2.A29 ; port RX.PER3_P
PERST#: P2.A11 ; port AUX.PERST#
PET0_N: P2.B15 ; port TX.PET0_N  [project net PCIE.PCIE_RX0_N]
PET0_P: P2.B14 ; port TX.PET0_P  [project net PCIE.PCIE_RX0_P]
PET1_N: P2.B20 ; port TX.PET1_N  [project net PCIE.PCIE_RX1_N]
PET1_P: P2.B19 ; port TX.PET1_P  [project net PCIE.PCIE_RX1_P]
PET2_N: P2.B24 ; port TX.PET2_N  [project net PCIE.PCIE_RX2_N]
PET2_P: P2.B23 ; port TX.PET2_P  [project net PCIE.PCIE_RX2_P]
PET3_N: P2.B28 ; port TX.PET3_N  [project net PCIE.PCIE_RX3_N]
PET3_P: P2.B27 ; port TX.PET3_P  [project net PCIE.PCIE_RX3_P]
PRSNT1#: P2.A1 P2.B31 ; port AUX.PRSNT1#, port AUX.PRSNT2#  [also labelled PRSNT2#]
REFCLK_N: P2.A14 ; port AUX.REFCLK-
REFCLK_P: P2.A13 ; port AUX.REFCLK+
SMCLK: P2.B5 ; port AUX.SMCLK
SMDAT: P2.B6 ; port AUX.SMDAT
WAKE#: P2.B11 ; port AUX.WAKE#

Not connected (* = marked no-connect by the designer): P2 A19* A32* B12* B17 B30*

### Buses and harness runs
bus JTAG[1..5]

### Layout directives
differential pair; differential pair class PCIe: PCIE.PCIE_RX0_N, PCIE.PCIE_RX0_P, PCIE.PCIE_RX1_N, PCIE.PCIE_RX1_P, PCIE.PCIE_RX2_N, PCIE.PCIE_RX2_P, PCIE.PCIE_RX3_N, PCIE.PCIE_RX3_P, PER0_N, PER0_P, PER1_N, PER1_P, PER2_N, PER2_P, PER3_N, PER3_P

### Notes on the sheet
- PCIe 4x Slot
- RSVD
- Labels drawn without touching a wire or pin: PRSNT2#

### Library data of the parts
LOGO?#3 = LIGO_logo
P2 = CMP-0001-00031-2: NL

## Sheet AD32_Power.SchDoc: Power Top
size B; Engineer: Daniel Sigg; Revision: 1; SheetNumber: 7; SheetTotal: 17; PageSetup: Record=PageOptions¦CenterHorizontal=True¦CenterVertical=True¦PrintScale=1.12¦XCorrection=1.00¦YCorrection=1.00¦PrintKind=0¦BorderSize=5000000¦LeftOffset=0¦BottomOffset=0¦Orientation=2¦PaperLength=1000¦PaperWidth=1000¦Scale=100¦PaperSource=7¦PrintQuality=-4¦MediaType=1¦DitherType=10¦PaperKind=Letter¦PrintScaleMode=1
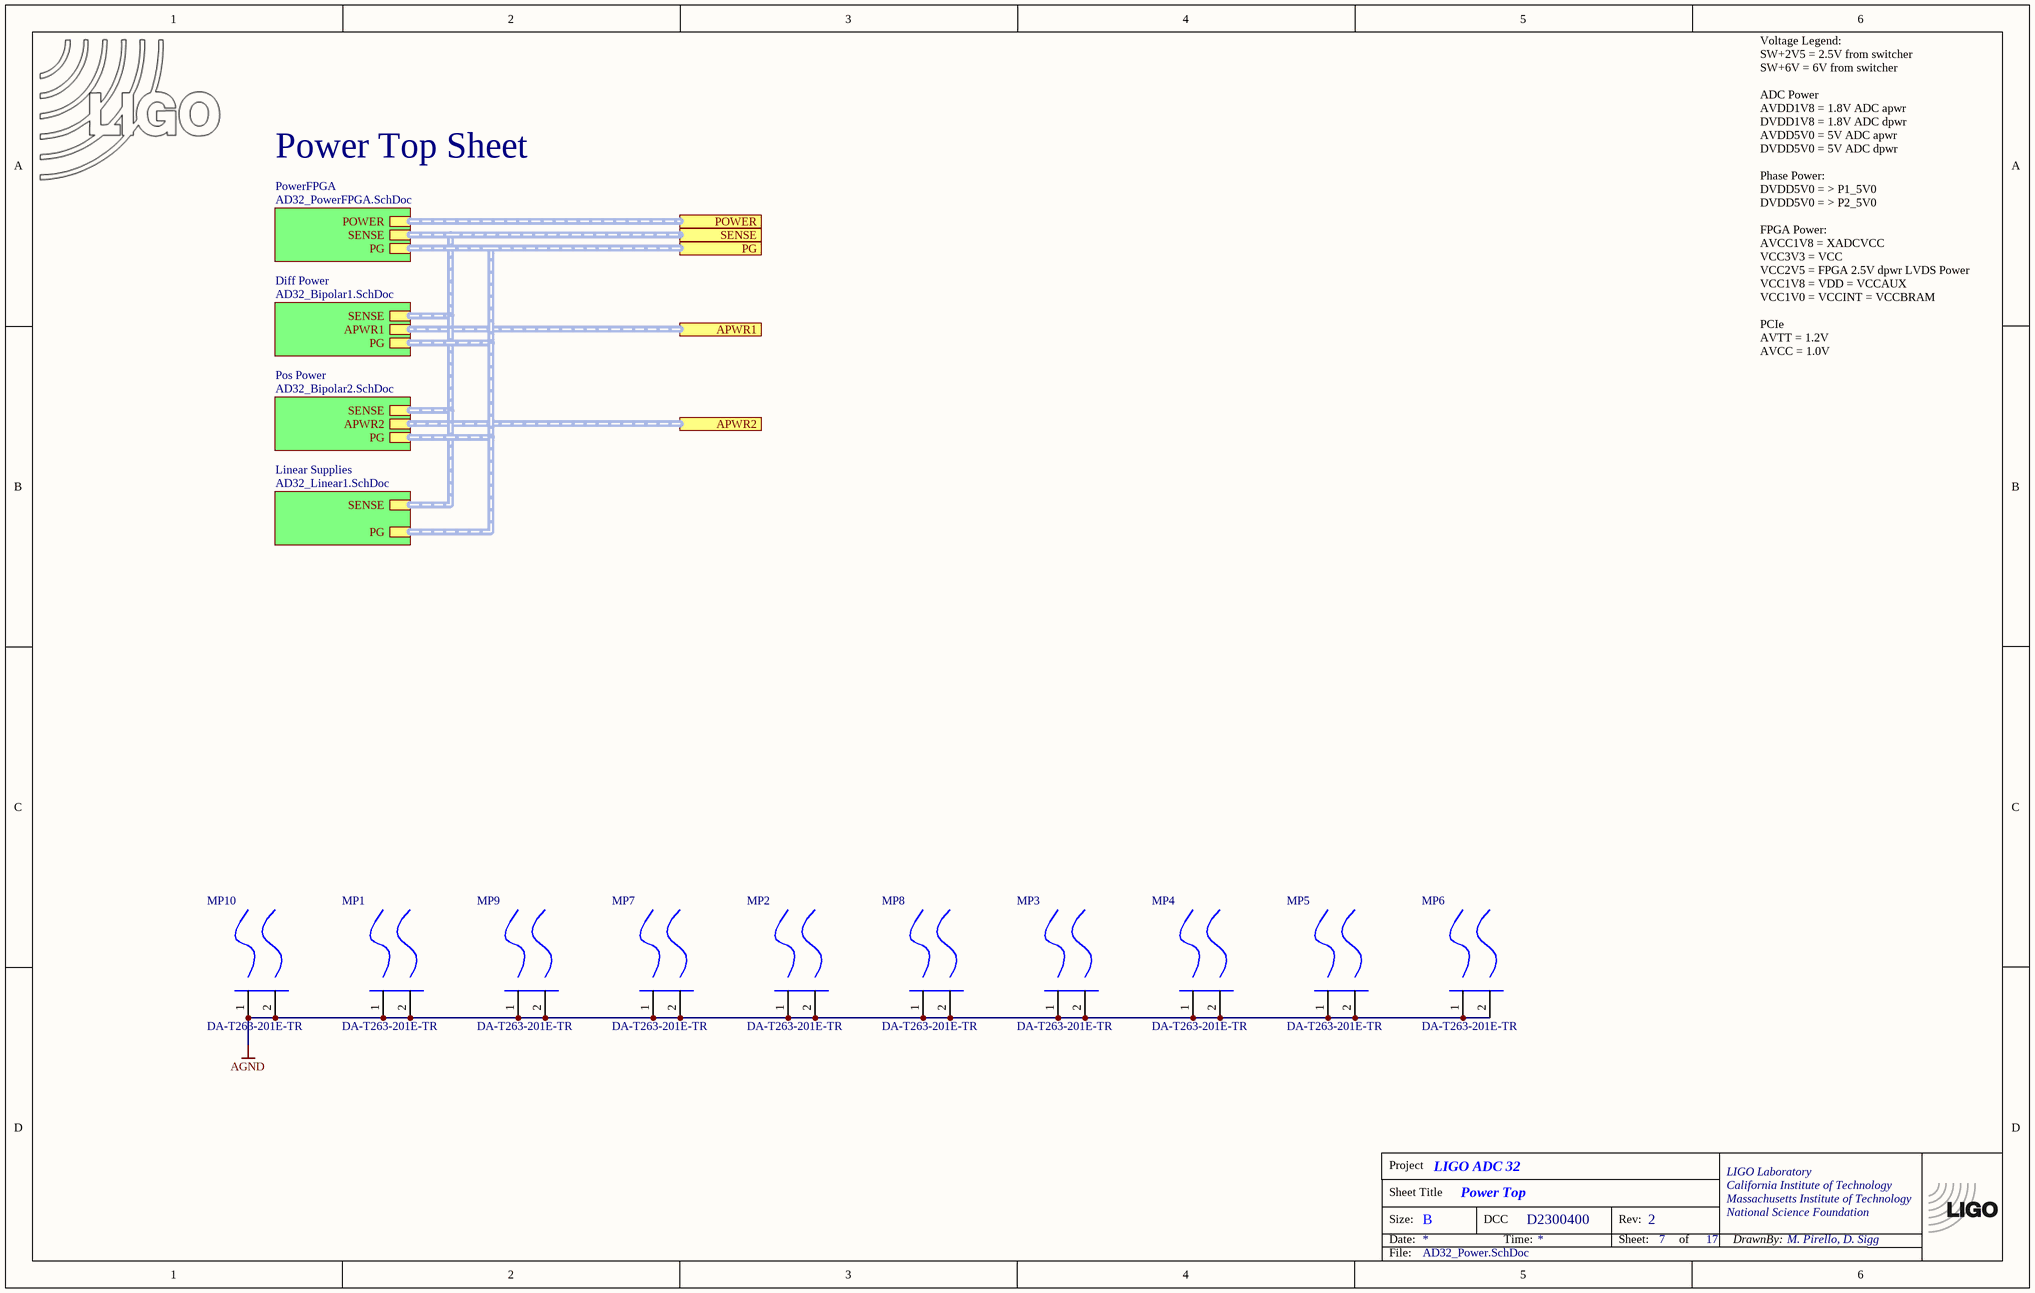
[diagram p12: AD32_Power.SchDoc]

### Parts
(Parts that share a designator on the sheet are numbered #1, #2 ... from top to bottom, then left to right.)
*?#9  TitleBlock  (value not drawn)  (graphical)
LOGO2#2  LIGO logo  [LIGO_LOGO]  (value not drawn)  (graphical)
MP1  DA-T263-201E-TR  [FP-DA-T263-201E-TR-MFG]
MP2  DA-T263-201E-TR  [FP-DA-T263-201E-TR-MFG]
MP3  DA-T263-201E-TR  [FP-DA-T263-201E-TR-MFG]
MP4  DA-T263-201E-TR  [FP-DA-T263-201E-TR-MFG]
MP5  DA-T263-201E-TR  [FP-DA-T263-201E-TR-MFG]
MP6  DA-T263-201E-TR  [FP-DA-T263-201E-TR-MFG]
MP7  DA-T263-201E-TR  [FP-DA-T263-201E-TR-MFG]
MP8  DA-T263-201E-TR  [FP-DA-T263-201E-TR-MFG]
MP9  DA-T263-201E-TR  [FP-DA-T263-201E-TR-MFG]
MP10  DA-T263-201E-TR  [FP-DA-T263-201E-TR-MFG]

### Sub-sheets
Diff Power = AD32_Bipolar1.SchDoc: APWR1 (harness APWR1), PG (harness APWR2), SENSE (harness SENSE)
Linear Supplies = AD32_Linear1.SchDoc: PG (harness APWR2), SENSE (harness SENSE)
Pos Power = AD32_Bipolar2.SchDoc: APWR2 (harness APWR2), PG (harness APWR2), SENSE (harness SENSE)
PowerFPGA = AD32_PowerFPGA.SchDoc: POWER (harness POWER), SENSE (harness SENSE), PG (harness APWR2)

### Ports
APWR1 (harness Inrush), APWR2 (harness Inrush), PG (harness Inrush), POWER (harness Inrush), SENSE (harness Inrush)

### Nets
AGND: MP1.1(MNT_1) MP1.2(MNT_2) MP2.1(MNT_1) MP2.2(MNT_2) MP3.1(MNT_1) MP3.2(MNT_2) MP4.1(MNT_1) MP4.2(MNT_2) MP5.1(MNT_1) MP5.2(MNT_2) MP6.1(MNT_1) MP6.2(MNT_2) MP7.1(MNT_1) MP7.2(MNT_2) MP8.1(MNT_1) MP8.2(MNT_2) MP9.1(MNT_1) MP9.2(MNT_2) MP10.1(MNT_1) MP10.2(MNT_2)

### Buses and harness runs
harness port APWR1 = sheet Diff Power/APWR1
harness port APWR2 = sheet Pos Power/APWR2
harness port PG = sheet Diff Power/PG = sheet Linear Supplies/PG = sheet Pos Power/PG = sheet PowerFPGA/PG
harness port POWER = sheet PowerFPGA/POWER
harness port SENSE = sheet Diff Power/SENSE = sheet Linear Supplies/SENSE = sheet Pos Power/SENSE = sheet PowerFPGA/SENSE

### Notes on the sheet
- Power Top Sheet
- Voltage Legend:
  SW+2V5 = 2.5V from switcher
  SW+6V = 6V from switcher
  ADC Power
  AVDD1V8 = 1.8V ADC apwr
  DVDD1V8 = 1.8V ADC dpwr
  AVDD5V0 = 5V ADC apwr
  DVDD5V0 = 5V ADC dpwr
  Phase Power:
  DVDD5V0 = > P1_5V0
  DVDD5V0 = > P2_5V0
  FPGA Power:
  AVCC1V8 = XADCVCC
  VCC3V3 = VCC
  VCC2V5 = FPGA 2.5V dpwr LVDS Power
  VCC1V8 = VDD = VCCAUX
  VCC1V0 = VCCINT = VCCBRAM
  PCIe
  AVTT = 1.2V
  AVCC = 1.0V

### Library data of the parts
LOGO2#2 = LIGO_logo
MP1-MP10 = CMP-33535-000006-1: HEATSINK FOR TO-263

## Sheet AD32_Bipolar1.SchDoc: Bipolar Analog Supply
size B; Engineer: Daniel Sigg; Revision: 1; SheetNumber: 10; SheetTotal: 17
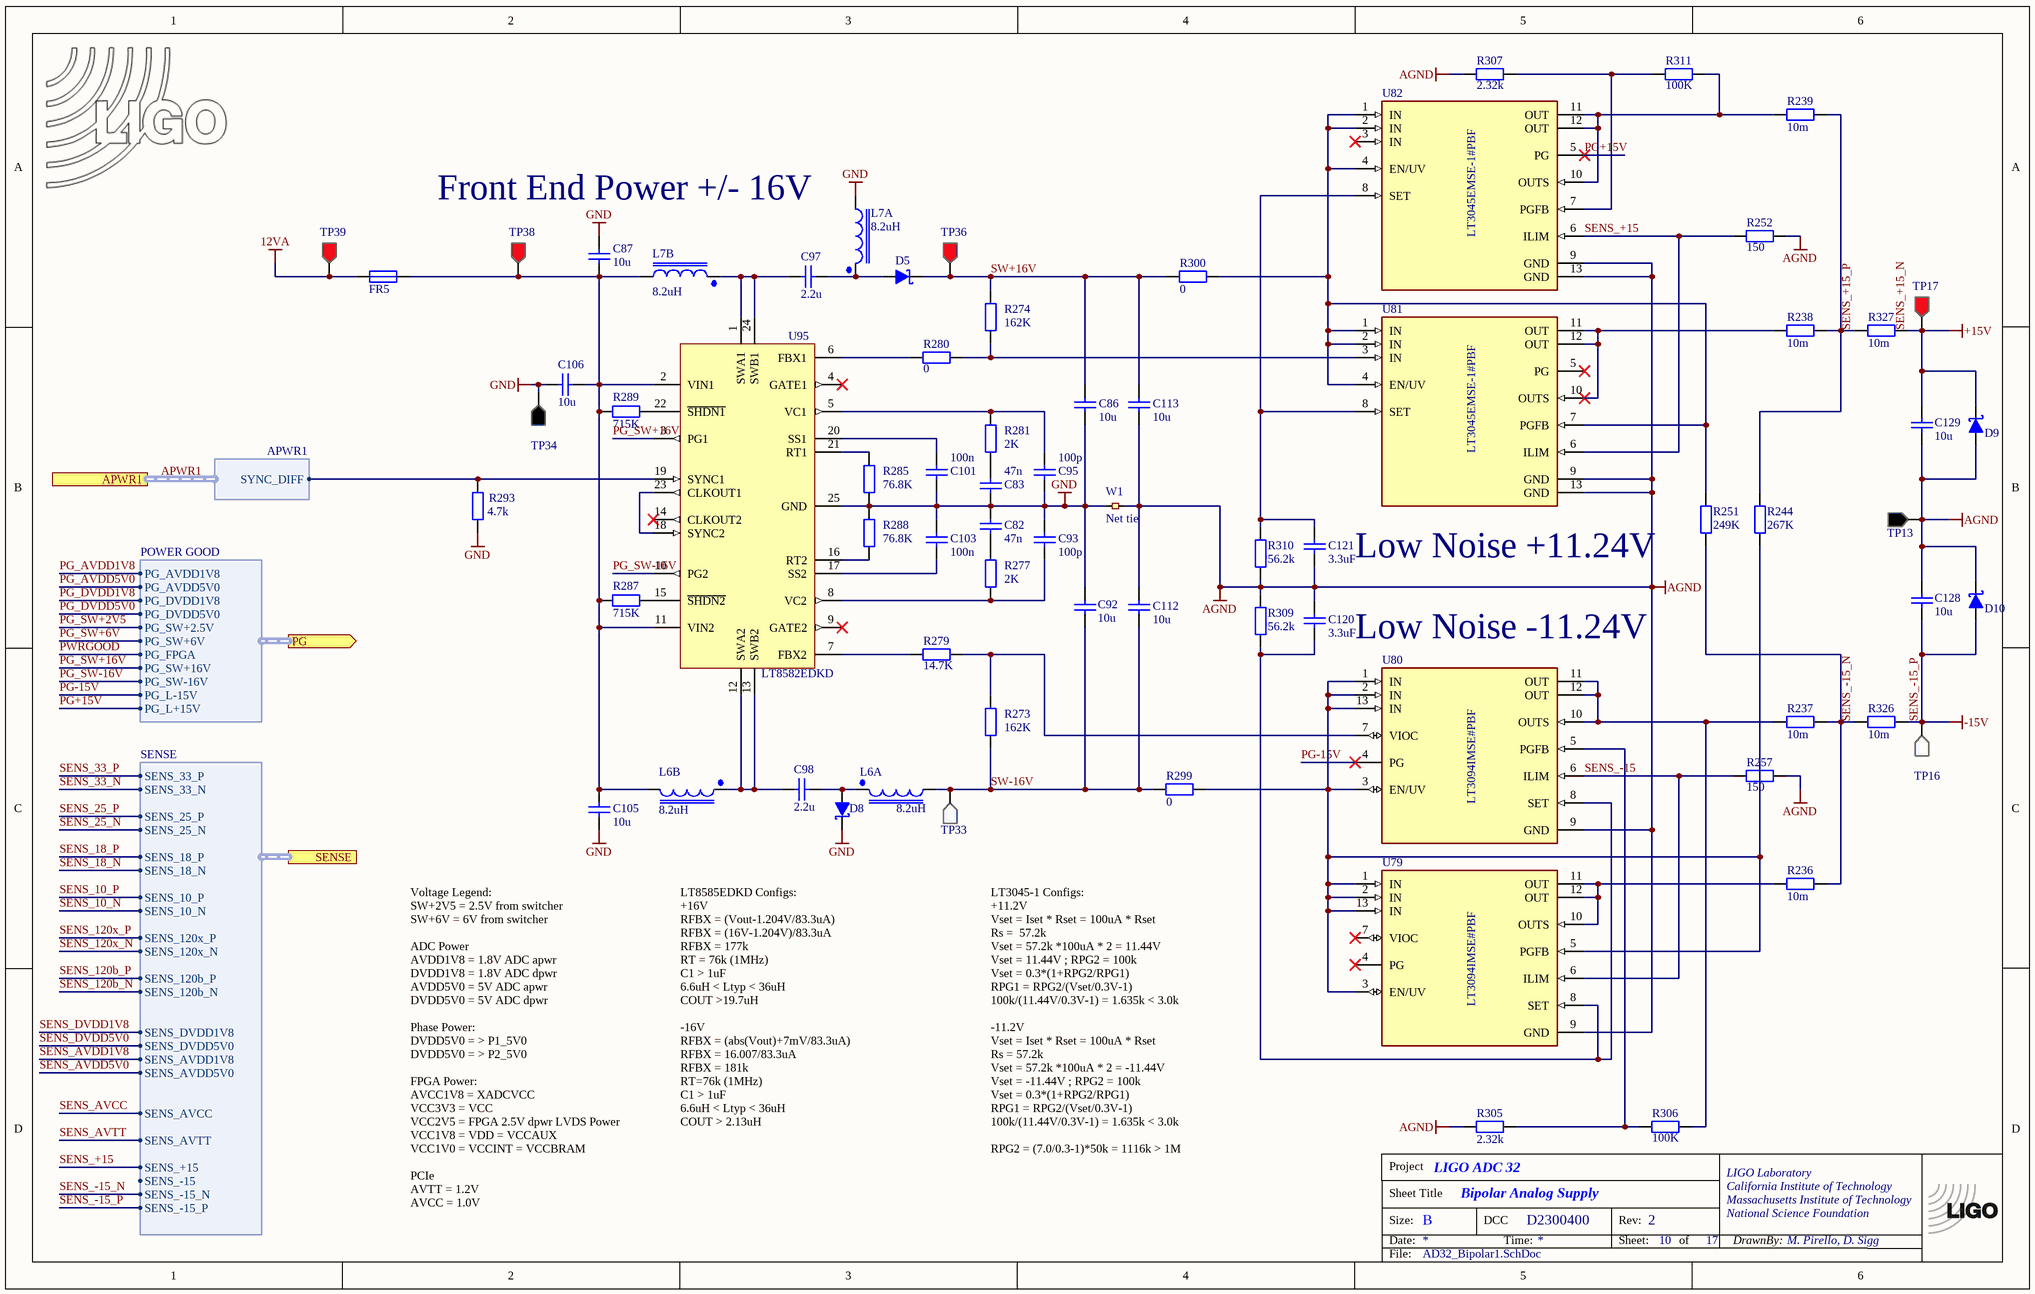
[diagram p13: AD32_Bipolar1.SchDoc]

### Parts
(Parts that share a designator on the sheet are numbered #1, #2 ... from top to bottom, then left to right.)
*?#10  TitleBlock  (value not drawn)  (graphical)
C82  47n  [CC1005-0402]
C83  47n  [CC1005-0402]
C86  10u  [CC3225-1210]
C87  10u  [CC3225-1210]
C92  10u  [CC3225-1210]
C93  100p  [CC1005-0402]
C95  100p  [CC1005-0402]
C97  2.2u  [CC3216-1206]
C98  2.2u  [CC3216-1206]
C101  100n  [CC1005-0402]
C103  100n  [CC1005-0402]
C105  10u  [CC3225-1210]
C106  10u  [CC3225-1210]
C112  10u  [CC3225-1210]
C113  10u  [CC3225-1210]
C120  3.3uF  [CC3225-1210]
C121  3.3uF  [CC3225-1210]
C128  10u  [CC3225-1210]
C129  10u  [CC3225-1210]
D5  Schottky DO-PowerDI123  [DO-PowerDI123]  (value not drawn)
D8  Schottky DO-PowerDI123  [DO-PowerDI123]  (value not drawn)
D9  shottky diode  [DO-SMA]  (value not drawn)
D10  shottky diode  [DO-SMA]  (value not drawn)
FR5  BLM31PG121  [CC3216-1206]  (value not drawn)
L6  8.2uH  [MSD7342]  (parts A,B of 2)
L7  8.2uH  [MSD7342]  (parts A,B of 2)
LOGO?#4  LIGO logo  [LIGO_LOGO]  (value not drawn)  (graphical)
R236  10m  [CR1608-0603]
R237  10m  [CR1608-0603]
R238  10m  [CR1608-0603]
R239  10m  [CR1608-0603]
R244  267K  [CR1005-0402]
R251  249K  [CR1005-0402]
R252  150  [CR1005-0402]
R257  150  [CR1005-0402]
R273  162K  [CR1005-0402]
R274  162K  [CR1005-0402]
R277  2K  [CR1005-0402]
R279  14.7K  [CR1005-0402]
R280  0  [CR1005-0402]
R281  2K  [CR1005-0402]
R285  76.8K  [CR1005-0402]
R287  715K  [CR1005-0402]
R288  76.8K  [CR1005-0402]
R289  715K  [CR1005-0402]
R293  4.7k  [CR1005-0402]
R299  0  [CR1608-0603]
R300  0  [CR1608-0603]
R305  2.32k  [CR1005-0402]
R306  100K  [CR1005-0402]
R307  2.32k  [CR1005-0402]
R309  56.2k  [CR1005-0402]
R310  56.2k  [CR1005-0402]
R311  100K  [CR1005-0402]
R326  10m  [CR1608-0603]
R327  10m  [CR1608-0603]
TP13  Testpoint  [TP1-BLK]  (value not drawn)
TP16  Testpoint  [TP1-WHT]  (value not drawn)
TP17  Testpoint  [TP1-RED]  (value not drawn)
TP33  Testpoint  [TP1-WHT]  (value not drawn)
TP34  Testpoint  [TP1-BLK]  (value not drawn)
TP36  Testpoint  [TP1-RED]  (value not drawn)
TP38  Testpoint  [TP1-RED]  (value not drawn)
TP39  Testpoint  [TP1-RED]  (value not drawn)
U79  LT3094IMSE#PBF  [FP-MSE-12-05-08-1666-IPC_B]
U80  LT3094IMSE#PBF  [FP-MSE-12-05-08-1666-IPC_B]
U81  LT3045EMSE-1#PBF  [FP-MSE-12-05-08-1666-IPC_B]
U82  LT3045EMSE-1#PBF  [FP-MSE-12-05-08-1666-IPC_B]
U95  LT8582EDKD  [DFN-24_DKD]
W1  Net tie  [NETTIE1_SMDTOP]  (net tie, no BOM)

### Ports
APWR1 (harness APWR1), PG (out, harness Power good), SENSE (harness SENSE)

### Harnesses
APWR1: SYNC_DIFF
SENSE: SENS_33_P, SENS_33_N, SENS_25_P, SENS_25_N, SENS_18_P, SENS_18_N, SENS_10_P, SENS_10_N, SENS_120x_P, SENS_120x_N, SENS_120b_P, SENS_120b_N, SENS_DVDD1V8, SENS_DVDD5V0, SENS_AVDD1V8, SENS_+15, SENS_-15, SENS_AVTT, SENS_AVCC, SENS_-15_N, SENS_-15_P, SENS_AVDD5V0
POWER GOOD: PG_AVDD5V0, PG_DVDD1V8, PG_DVDD5V0, PG_SW+2.5V, PG_SW+6V, PG_FPGA, PG_SW+16V, PG_SW-16V, PG_L-15V, PG_L+15V, PG_AVDD1V8

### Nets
12VA: FR5.1 TP39.1
+15V: C129.2 D9.2(K) R327.1 TP17.1  [also labelled SENS_+15_N]
-15V: C128.1 D10.1(A) R326.1 TP16.1 ; port SENSE.SENS_-15_P  [also labelled SENS_-15_P]
AGND: C112.2 C113.1 C120.2 C121.1 C128.2 C129.1 D9.1(A) D10.2(K) R252.1 R257.1 R305.2 R307.2 R309.2 R310.1 TP13.1 U79.9(GND) U80.9(GND) U81.9(GND) U81.13(GND) U82.9(GND) U82.13(GND) W1.2
GND: C82.2 C83.1 C86.1 C87.2 C92.2 C93.2 C95.1 C101.1 C103.2 C105.1 C106.2 D8.2(K) L7.3 R285.1 R288.2 R293.2 TP34.1 U95.25(GND) W1.1
APWR1.SYNC_DIFF: R293.1 U95.19(SYNC1) ; port APWR1.SYNC_DIFF
PG+15V: U82.5(PG) ; port PG.PG_L+15V  [project net PG.PG_L+15V]
PG-15V: U80.4(PG) ; port PG.PG_L-15V  [project net PG.PG_L-15V]
PG_SW+16V: U95.3(PG1) ; port PG.PG_SW+16V  [project net PG.PG_SW+16V]
PG_SW-16V: U95.10(PG2) ; port PG.PG_SW-16V  [project net PG.PG_SW-16V]
SENS_+15: R252.2 U81.6(ILIM) U82.6(ILIM) ; port SENSE.SENS_+15  [project net SENSE.SENS_+15]
SENS_+15_P: R238.1 R239.1 R244.2 R327.2
SENS_-15: R257.2 U79.6(ILIM) U80.6(ILIM)
SENS_-15_N: R236.1 R237.1 R251.1 R326.2 ; port SENSE.SENS_-15_N  [project net SENSE.SENS_-15_N]
SW+16V: C86.2 C113.2 D5.2(K) R274.2 R300.2 TP36.1
SW-16V: C92.1 C112.1 L6.3 R273.1 R299.2 TP33.1
NetC82_1: C82.1 R277.2
NetC83_2: C83.2 R281.1
NetC87_1: C87.1 C105.2 C106.1 FR5.2 L6.4 L7.4 R287.2 R289.2 TP38.1 U95.2(VIN1) U95.11(VIN2)
NetC93_1: C93.1 R277.1 U95.8(VC2)
NetC95_2: C95.2 R281.2 U95.5(VC1)
NetC97_1: C97.1 D5.1(A) L7.1
NetC97_2: C97.2 L7.2 U95.1(SWA1) U95.24(SWB1)
NetC98_1: C98.1 D8.1(A) L6.1
NetC98_2: C98.2 L6.2 U95.12(SWA2) U95.13(SWB2)
NetC101_2: C101.2 U95.20(SS1)
NetC103_1: C103.1 U95.17(SS2)
NetC120_1: C120.1 R309.1 U79.8(SET) U80.8(SET)
NetC121_2: C121.2 R310.2 U81.8(SET) U82.8(SET)
NetR236_2: R236.2 U79.10(OUTS) U79.11(OUT) U79.12(OUT)
NetR237_2: R237.2 R306.1 U80.10(OUTS) U80.11(OUT) U80.12(OUT)
NetR238_2: R238.2 U81.10(OUTS) U81.11(OUT) U81.12(OUT)
NetR239_2: R239.2 R311.1 U82.10(OUTS) U82.11(OUT) U82.12(OUT)
NetR244_1: R244.1 R299.1 U79.1(IN) U79.2(IN) U79.3(EN/UV) U79.5(PGFB) U79.13(IN) U80.1(IN) U80.2(IN) U80.3(EN/UV) U80.13(IN)
NetR251_2: R251.2 R300.1 U81.1(IN) U81.2(IN) U81.4(EN/UV) U81.7(PGFB) U82.1(IN) U82.2(IN) U82.4(EN/UV)
NetR273_2: R273.2 R279.1 U80.7(VIOC)
NetR274_1: R274.1 R280.1 U81.3(IN)
NetR279_2: R279.2 U95.7(FBX2)
NetR280_2: R280.2 U95.6(FBX1)
NetR285_2: R285.2 U95.21(RT1)
NetR287_1: R287.1 U95.15(~{SHDN2})
NetR288_1: R288.1 U95.16(RT2)
NetR289_1: R289.1 U95.22(~{SHDN1})
NetR305_1: R305.1 R306.2 U80.5(PGFB)
NetR307_1: R307.1 R311.2 U82.7(PGFB)
NetU95_18: U95.18(SYNC2) U95.23(CLKOUT1)

Not connected (* = marked no-connect by the designer): U79 4(PG)* 7(VIOC)*; U81 5(PG)*; U82 3(IN)*; U95 4(GATE1)* 9(GATE2)* 14(CLKOUT2)*

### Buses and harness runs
harness APWR1 = port APWR1

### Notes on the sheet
- (near L7) Front End Power +/- 16V
- Low Noise +11.24V
- Low Noise -11.24V
- LT8585EDKD Configs:
  +16V
  RFBX = (Vout-1.204V/83.3uA)
  RFBX = (16V-1.204V)/83.3uA
  RFBX = 177k
  RT = 76k (1MHz)
  C1 > 1uF
  6.6uH < Ltyp < 36uH
  COUT >19.7uH
  -16V
  RFBX = (abs(Vout)+7mV/83.3uA)
  RFBX = 16.007/83.3uA
  RFBX = 181k
  RT=76k (1MHz)
  C1 > 1uF
  6.6uH < Ltyp < 36uH
  COUT > 2.13uH
- LT3045-1 Configs:
  +11.2V
  Vset = Iset * Rset = 100uA * Rset
  Rs =  57.2k
  Vset = 57.2k *100uA * 2 = 11.44V
  Vset = 11.44V ; RPG2 = 100k
  Vset = 0.3*(1+RPG2/RPG1)
  RPG1 = RPG2/(Vset/0.3V-1)
  100k/(11.44V/0.3V-1) = 1.635k < 3.0k
  -11.2V
  Vset = Iset * Rset = 100uA * Rset
  Rs = 57.2k
  Vset = 57.2k *100uA * 2 = -11.44V
  Vset = -11.44V ; RPG2 = 100k
  Vset = 0.3*(1+RPG2/RPG1)
  RPG1 = RPG2/(Vset/0.3V-1)
  100k/(11.44V/0.3V-1) = 1.635k < 3.0k
  RPG2 = (7.0/0.3-1)*50k = 1116k > 1M
- Voltage Legend:
  SW+2V5 = 2.5V from switcher
  SW+6V = 6V from switcher
  ADC Power
  AVDD1V8 = 1.8V ADC apwr
  DVDD1V8 = 1.8V ADC dpwr
  AVDD5V0 = 5V ADC apwr
  DVDD5V0 = 5V ADC dpwr
  Phase Power:
  DVDD5V0 = > P1_5V0
  DVDD5V0 = > P2_5V0
  FPGA Power:
  AVCC1V8 = XADCVCC
  VCC3V3 = VCC
  VCC2V5 = FPGA 2.5V dpwr LVDS Power
  VCC1V8 = VDD = VCCAUX
  VCC1V0 = VCCINT = VCCBRAM
  PCIe
  AVTT = 1.2V
  AVCC = 1.0V

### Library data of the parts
C82 C83 = ChipCap: C0402 47n; Part Number: 0402B473J250CT
C86 C87 C92 C105 C106 C112 C113 C128 C129 = ChipCap: C1210 10u; Part Number: CL32B106KAULNNE
C93 C95 = ChipCap: C0402 100p; Part Number: KGM05ACG1H101JH
C97 C98 = ChipCap: C1206 2.2u; Part Number: C1206C225J5RECAUTO
C101 C103 = ChipCap: C0402 100n; Part Number: CL05B104KA5NNNC
C120 C121 = ChipCap: C1210 3.3u Ruby; Part Number: 16MU335MB33225
D5 D8 = DIODE_SHOTTKY: Part Number: DFLS230-7
D9 D10 = DIODE_SHOTTKY: Single shottky diode; Part Number: CDBA340L-G
FR5 = BLM31PG121SN1: as FR1 on sheet AD32_PHASE
L6 L7 = MSD7342: Shielded Coupled Inductors, MSD7342 series 8.2uH; Part Number: MSD7342-822MLC
LOGO?#4 = LIGO_logo
R236-R239 R326 R327 = ChipRes1: R0603 10m; Part Number: CFN0603AFZ-R010ELF
R244 = ChipRes1: R0402 267k; Part Number: ERJ-2RKF2673X
R251 = ChipRes1: R0402 249k; Part Number: RP73PF1E249KBTD
R252 R257 = ChipRes1: R0402 150; Part Number: ERA-2AEB151X
R273 R274 = ChipRes1: R0402 162k; Part Number: RP73PF1E162KBTD
R277 R281 = ChipRes1: R0402 2k; Part Number: ERA-2AEB202X
R279 = ChipRes1: R0402 14.7k; Part Number: RT0402BRD0714K7L
R280 = ChipRes1: R0402 0; Part Number: AC0402FR-070RL
R285 R288 = ChipRes1: R0402 76.8k; Part Number: RT0402DRE0776K8L
R287 R289 = ChipRes1: R0402 715k; Part Number: RC0402FR-07715KL
R293 = ChipRes1: R0402 4.7k; Part Number: ERA-2AED472X
R299 R300 = ChipRes1: R0603 0; Part Number: RC0603JR-070RL
R305 R307 = ChipRes1: R0402 2.32k; Part Number: RT0402BRD072K32L
R306 R311 = ChipRes1: R0402 100k; Part Number: ERA-2AEB104X
R309 R310 = ChipRes1: R0402 56.2k; Part Number: RK73H1ETTP5622F
TP13 TP34 = TP_GND: as TP32 on sheet AD32_PCIE_HL
TP16 TP33 = TP_NEGATIVE: Testpoint, white; Part Number: Keystone / 5002
TP17 TP36 TP38 TP39 = TP_POSITIVE: as TP4 on sheet AD32_PHASE
U79 U80 = CMP-09138-000085-1: IC REG LIN NEG ADJ 500MA 12MSOP
U81 U82 = CMP-09138-000053-1: IC REG LINEAR 0V 500MA 12MSOP
U95 = LT8582: Dual 3A Boost/Inverting/SEPIC DC/DC Converter with Fault Protection; Part Number: LT8582EDKD#PBF
W1 = NetTie1_small: NL

## Sheet AD32_Linear1.SchDoc: Linear Supplies
size B; Engineer: Daniel Sigg; SheetNumber: 8; SheetTotal: 17
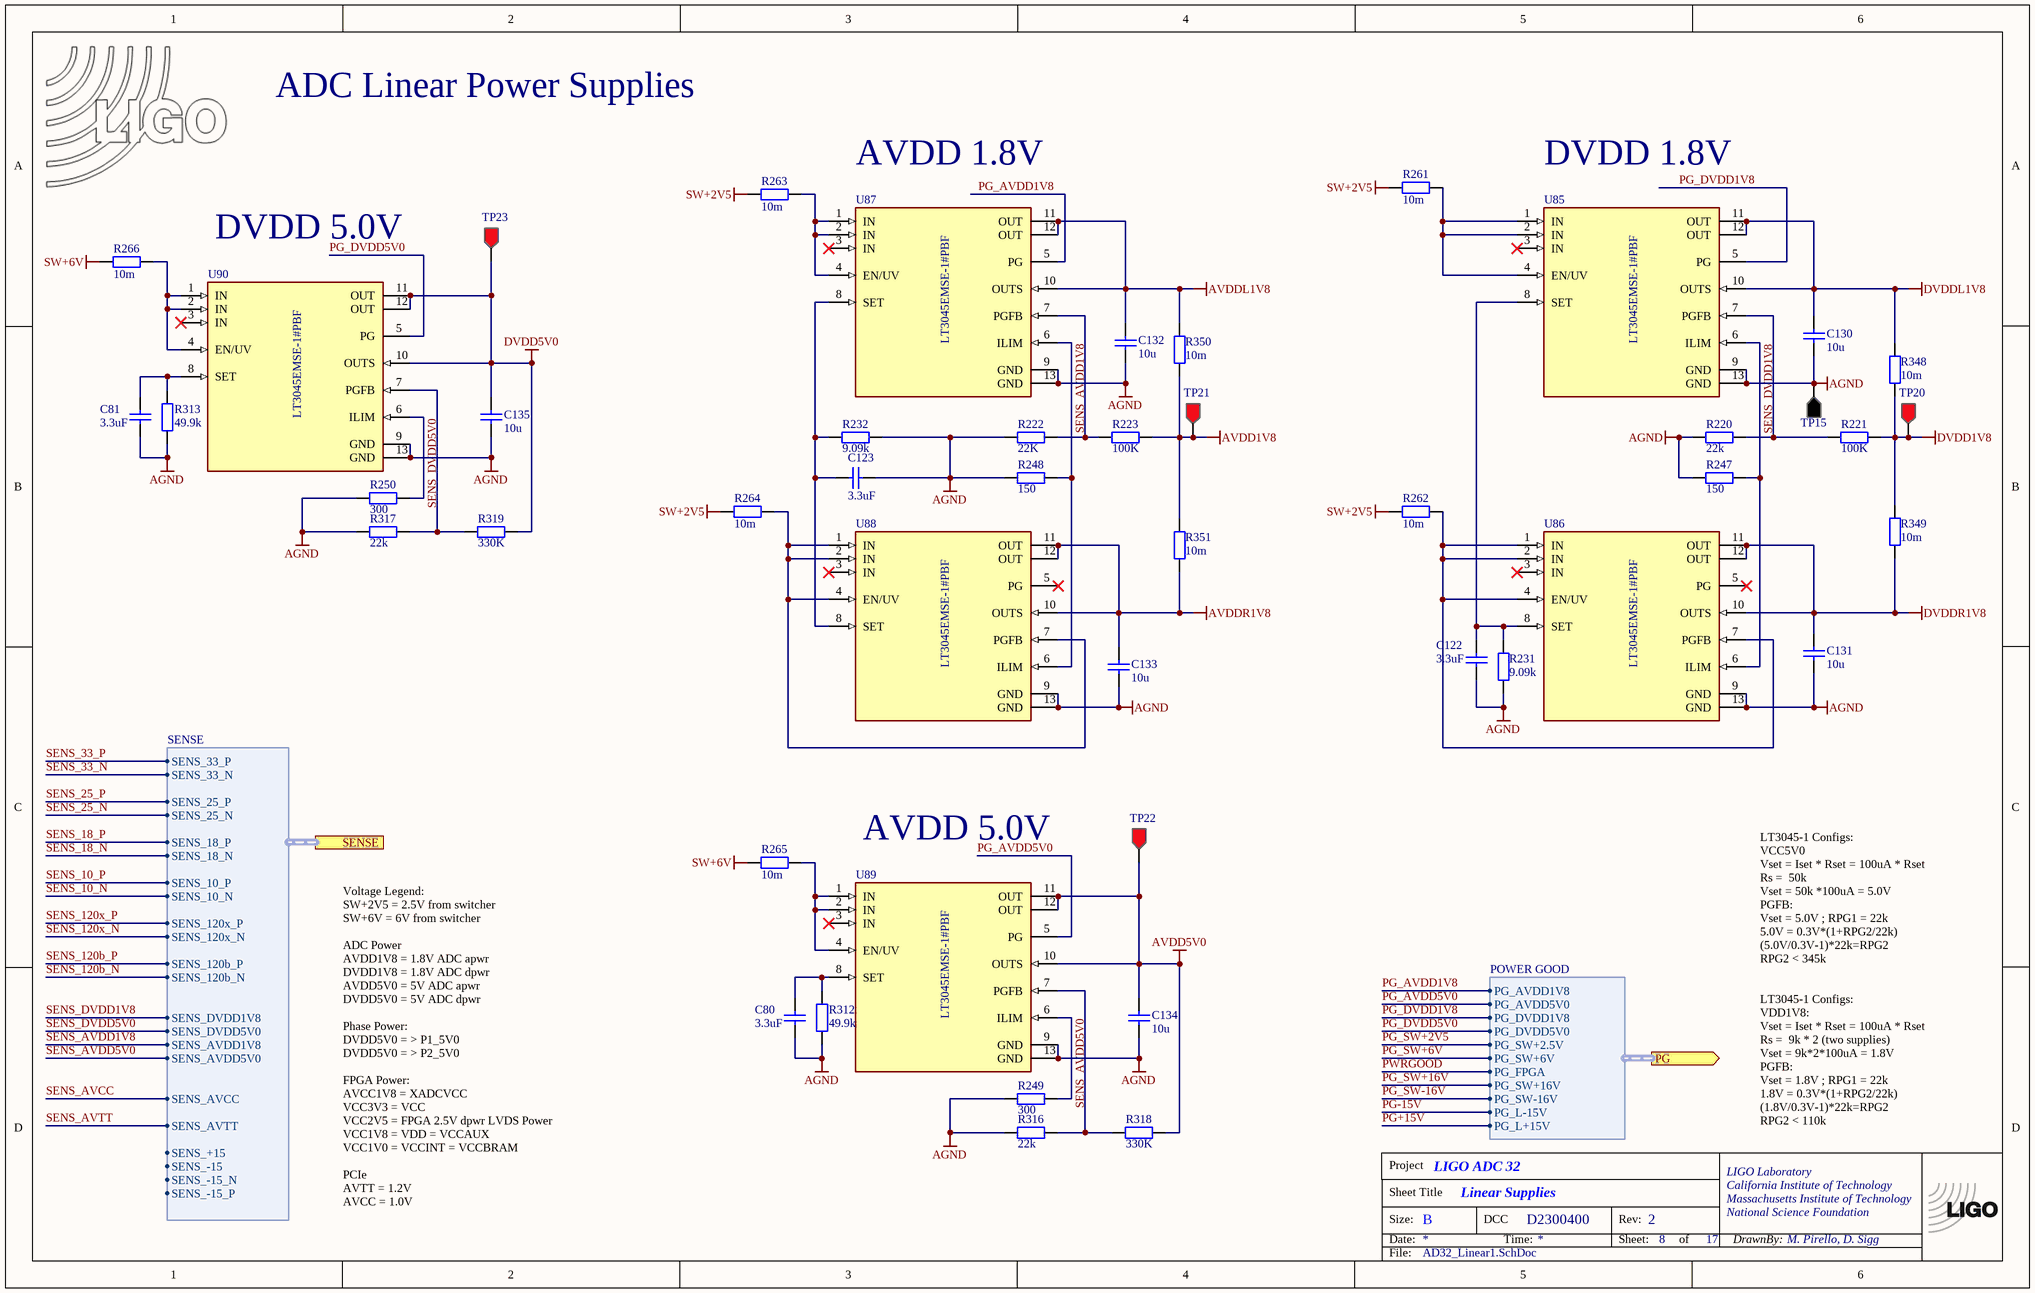
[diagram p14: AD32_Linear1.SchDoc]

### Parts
(Parts that share a designator on the sheet are numbered #1, #2 ... from top to bottom, then left to right.)
*?#11  TitleBlock  (value not drawn)  (graphical)
C80  3.3uF  [CC3225-1210]
C81  3.3uF  [CC3225-1210]
C122  3.3uF  [CC3225-1210]
C123  3.3uF  [CC3225-1210]
C130  10u  [CC3225-1210]
C131  10u  [CC3225-1210]
C132  10u  [CC3225-1210]
C133  10u  [CC3225-1210]
C134  10u  [CC3225-1210]
C135  10u  [CC3225-1210]
LOGO?#5  LIGO logo  [LIGO_LOGO]  (value not drawn)  (graphical)
R220  22k  [CR1005-0402]
R221  100K  [CR1005-0402]
R222  22K  [CR1005-0402]
R223  100K  [CR1005-0402]
R231  9.09k  [CR1608-0603]
R232  9.09k  [CR1608-0603]
R247  150  [CR1005-0402]
R248  150  [CR1005-0402]
R249  300  [CR1005-0402]
R250  300  [CR1005-0402]
R261  10m  [CR1608-0603]
R262  10m  [CR1608-0603]
R263  10m  [CR1608-0603]
R264  10m  [CR1608-0603]
R265  10m  [CR1608-0603]
R266  10m  [CR1608-0603]
R312  49.9k  [CR1005-0402]
R313  49.9k  [CR1005-0402]
R316  22k  [CR1005-0402]
R317  22k  [CR1005-0402]
R318  330K  [CR1005-0402]
R319  330K  [CR1005-0402]
R348  10m  [CR1608-0603]
R349  10m  [CR1608-0603]
R350  10m  [CR1608-0603]
R351  10m  [CR1608-0603]
TP15  Testpoint  [TP1-BLK]  (value not drawn)
TP20  Testpoint  [TP1-RED]  (value not drawn)
TP21  Testpoint  [TP1-RED]  (value not drawn)
TP22  Testpoint  [TP1-RED]  (value not drawn)
TP23  Testpoint  [TP1-RED]  (value not drawn)
U85  LT3045EMSE-1#PBF  [FP-MSE-12-05-08-1666-IPC_B]
U86  LT3045EMSE-1#PBF  [FP-MSE-12-05-08-1666-IPC_B]
U87  LT3045EMSE-1#PBF  [FP-MSE-12-05-08-1666-IPC_B]
U88  LT3045EMSE-1#PBF  [FP-MSE-12-05-08-1666-IPC_B]
U89  LT3045EMSE-1#PBF  [FP-MSE-12-05-08-1666-IPC_B]
U90  LT3045EMSE-1#PBF  [FP-MSE-12-05-08-1666-IPC_B]

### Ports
PG (out, harness Power good), SENSE (harness SENSE)

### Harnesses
POWER GOOD: PG_AVDD5V0, PG_DVDD1V8, PG_DVDD5V0, PG_SW+2.5V, PG_SW+6V, PG_FPGA, PG_SW+16V, PG_SW-16V, PG_L-15V, PG_L+15V, PG_AVDD1V8
SENSE: SENS_33_P, SENS_33_N, SENS_25_P, SENS_25_N, SENS_18_P, SENS_18_N, SENS_10_P, SENS_10_N, SENS_120x_P, SENS_120x_N, SENS_120b_P, SENS_120b_N, SENS_DVDD1V8, SENS_DVDD5V0, SENS_AVDD1V8, SENS_+15, SENS_-15, SENS_AVTT, SENS_AVCC, SENS_-15_N, SENS_-15_P, SENS_AVDD5V0

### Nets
AGND: C80.1 C81.1 C122.1 C123.1 C130.1 C131.1 C132.1 C133.1 C134.1 C135.1 R220.2 R222.2 R231.2 R232.1 R247.2 R248.2 R249.2 R250.2 R312.1 R313.1 R316.2 R317.2 TP15.1 U85.9(GND) U85.13(GND) U86.9(GND) U86.13(GND) U87.9(GND) U87.13(GND) U88.9(GND) U88.13(GND) U89.9(GND) U89.13(GND) U90.9(GND) U90.13(GND)
AVDD1V8: R223.1 R350.2 R351.1 TP21.1
AVDD5V0: C134.2 R318.1 TP22.1 U89.10(OUTS) U89.11(OUT) U89.12(OUT)
AVDDL1V8: C132.2 R350.1 U87.10(OUTS) U87.11(OUT) U87.12(OUT)
AVDDR1V8: C133.2 R351.2 U88.10(OUTS) U88.11(OUT) U88.12(OUT)
DVDD1V8: R221.1 R348.2 R349.1 TP20.1
DVDD5V0: C135.2 R319.1 TP23.1 U90.10(OUTS) U90.11(OUT) U90.12(OUT)
DVDDL1V8: C130.2 R348.1 U85.10(OUTS) U85.11(OUT) U85.12(OUT)
DVDDR1V8: C131.2 R349.2 U86.10(OUTS) U86.11(OUT) U86.12(OUT)
SW+2V5: R261.2 R262.2 R263.2 R264.2
SW+6V: R265.2 R266.2
PG_AVDD1V8: U87.5(PG) ; port PG.PG_AVDD1V8  [project net PG.PG_AVDD1V8]
PG_AVDD5V0: U89.5(PG) ; port PG.PG_AVDD5V0  [project net PG.PG_AVDD5V0]
PG_DVDD1V8: U85.5(PG) ; port PG.PG_DVDD1V8  [project net PG.PG_DVDD1V8]
PG_DVDD5V0: U90.5(PG) ; port PG.PG_DVDD5V0  [project net PG.PG_DVDD5V0]
SENS_AVDD1V8: R248.1 U87.6(ILIM) U88.6(ILIM) ; port SENSE.SENS_AVDD1V8  [project net SENSE.SENS_AVDD1V8]
SENS_AVDD5V0: R249.1 U89.6(ILIM) ; port SENSE.SENS_AVDD5V0  [project net SENSE.SENS_AVDD5V0]
SENS_DVDD1V8: R247.1 U85.6(ILIM) U86.6(ILIM) ; port SENSE.SENS_DVDD1V8  [project net SENSE.SENS_DVDD1V8]
SENS_DVDD5V0: R250.1 U90.6(ILIM) ; port SENSE.SENS_DVDD5V0  [project net SENSE.SENS_DVDD5V0]
NetC80_2: C80.2 R312.2 U89.8(SET)
NetC81_2: C81.2 R313.2 U90.8(SET)
NetC122_2: C122.2 R231.1 U85.8(SET) U86.8(SET)
NetC123_2: C123.2 R232.2 U87.8(SET) U88.8(SET)
NetR220_1: R220.1 R221.2 U85.7(PGFB)
NetR222_1: R222.1 R223.2 U87.7(PGFB)
NetR261_1: R261.1 U85.1(IN) U85.2(IN) U85.4(EN/UV)
NetR262_1: R262.1 U86.1(IN) U86.2(IN) U86.4(EN/UV) U86.7(PGFB)
NetR263_1: R263.1 U87.1(IN) U87.2(IN) U87.4(EN/UV)
NetR264_1: R264.1 U88.1(IN) U88.2(IN) U88.4(EN/UV) U88.7(PGFB)
NetR265_1: R265.1 U89.1(IN) U89.2(IN) U89.4(EN/UV)
NetR266_1: R266.1 U90.1(IN) U90.2(IN) U90.4(EN/UV)
NetR316_1: R316.1 R318.2 U89.7(PGFB)
NetR317_1: R317.1 R319.2 U90.7(PGFB)

Not connected (* = marked no-connect by the designer): U85 3(IN)*; U86 3(IN)* 5(PG)*; U87 3(IN)*; U88 3(IN)* 5(PG)*; U89 3(IN)*; U90 3(IN)*

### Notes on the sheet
- ADC Linear Power Supplies
- AVDD 1.8V
- (near U85) DVDD 1.8V
- (near U90) DVDD 5.0V
- (near U89) AVDD 5.0V
- LT3045-1 Configs:
  VCC5V0
  Vset = Iset * Rset = 100uA * Rset
  Rs =  50k
  Vset = 50k *100uA = 5.0V
  PGFB:
  Vset = 5.0V ; RPG1 = 22k
  5.0V = 0.3V*(1+RPG2/22k)
  (5.0V/0.3V-1)*22k=RPG2
  RPG2 < 345k
- LT3045-1 Configs:
  VDD1V8:
  Vset = Iset * Rset = 100uA * Rset
  Rs =  9k * 2 (two supplies)
  Vset = 9k*2*100uA = 1.8V
  PGFB:
  Vset = 1.8V ; RPG1 = 22k
  1.8V = 0.3V*(1+RPG2/22k)
  (1.8V/0.3V-1)*22k=RPG2
  RPG2 < 110k
- Voltage Legend:
  SW+2V5 = 2.5V from switcher
  SW+6V = 6V from switcher
  ADC Power
  AVDD1V8 = 1.8V ADC apwr
  DVDD1V8 = 1.8V ADC dpwr
  AVDD5V0 = 5V ADC apwr
  DVDD5V0 = 5V ADC dpwr
  Phase Power:
  DVDD5V0 = > P1_5V0
  DVDD5V0 = > P2_5V0
  FPGA Power:
  AVCC1V8 = XADCVCC
  VCC3V3 = VCC
  VCC2V5 = FPGA 2.5V dpwr LVDS Power
  VCC1V8 = VDD = VCCAUX
  VCC1V0 = VCCINT = VCCBRAM
  PCIe
  AVTT = 1.2V
  AVCC = 1.0V

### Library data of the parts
C80 C81 C122 C123 = ChipCap: as C120 on sheet AD32_Bipolar1
C130-C135 = ChipCap: C1210 10u; Part Number: CL32B106KAULNNE
LOGO?#5 = LIGO_logo
R220 R222 R316 R317 = ChipRes1: R0402 22k; Part Number: ERA-2AED223X
R221 R223 = ChipRes1: R0402 100k; Part Number: ERA-2AEB104X
R231 R232 = ChipRes1: R0603 9.09k; Part Number: ERA-3AEB9091V
R247 R248 = ChipRes1: R0402 150; Part Number: ERA-2AEB151X
R249 R250 = ChipRes1: R0402 300; Part Number: RR05P300DCT-ND
R261-R266 R348-R351 = ChipRes1: as R236 on sheet AD32_Bipolar1
R312 R313 = ChipRes1: R0402 49.9k; Part Number: RR0510P-4992-D
R318 R319 = ChipRes1: R0402 330k; Part Number: MCS0402MD3303BE000
TP15 = TP_GND: as TP32 on sheet AD32_PCIE_HL
TP20-TP23 = TP_POSITIVE: as TP4 on sheet AD32_PHASE
U85-U90 = CMP-09138-000053-1: IC REG LINEAR 0V 500MA 12MSOP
